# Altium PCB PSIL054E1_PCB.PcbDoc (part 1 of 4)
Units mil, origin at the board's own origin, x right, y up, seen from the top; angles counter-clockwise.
Board outline 2080 x 2700 mil, 8 copper layers (SSTXRX1, GND Plane 1, High Speed, GND Plane 2, Power 1, Power 2, GND Plane 3, SSTXRX2), stack 58.12 mil thick; 247 components, 148 nets, 834 pads, 632 vias.
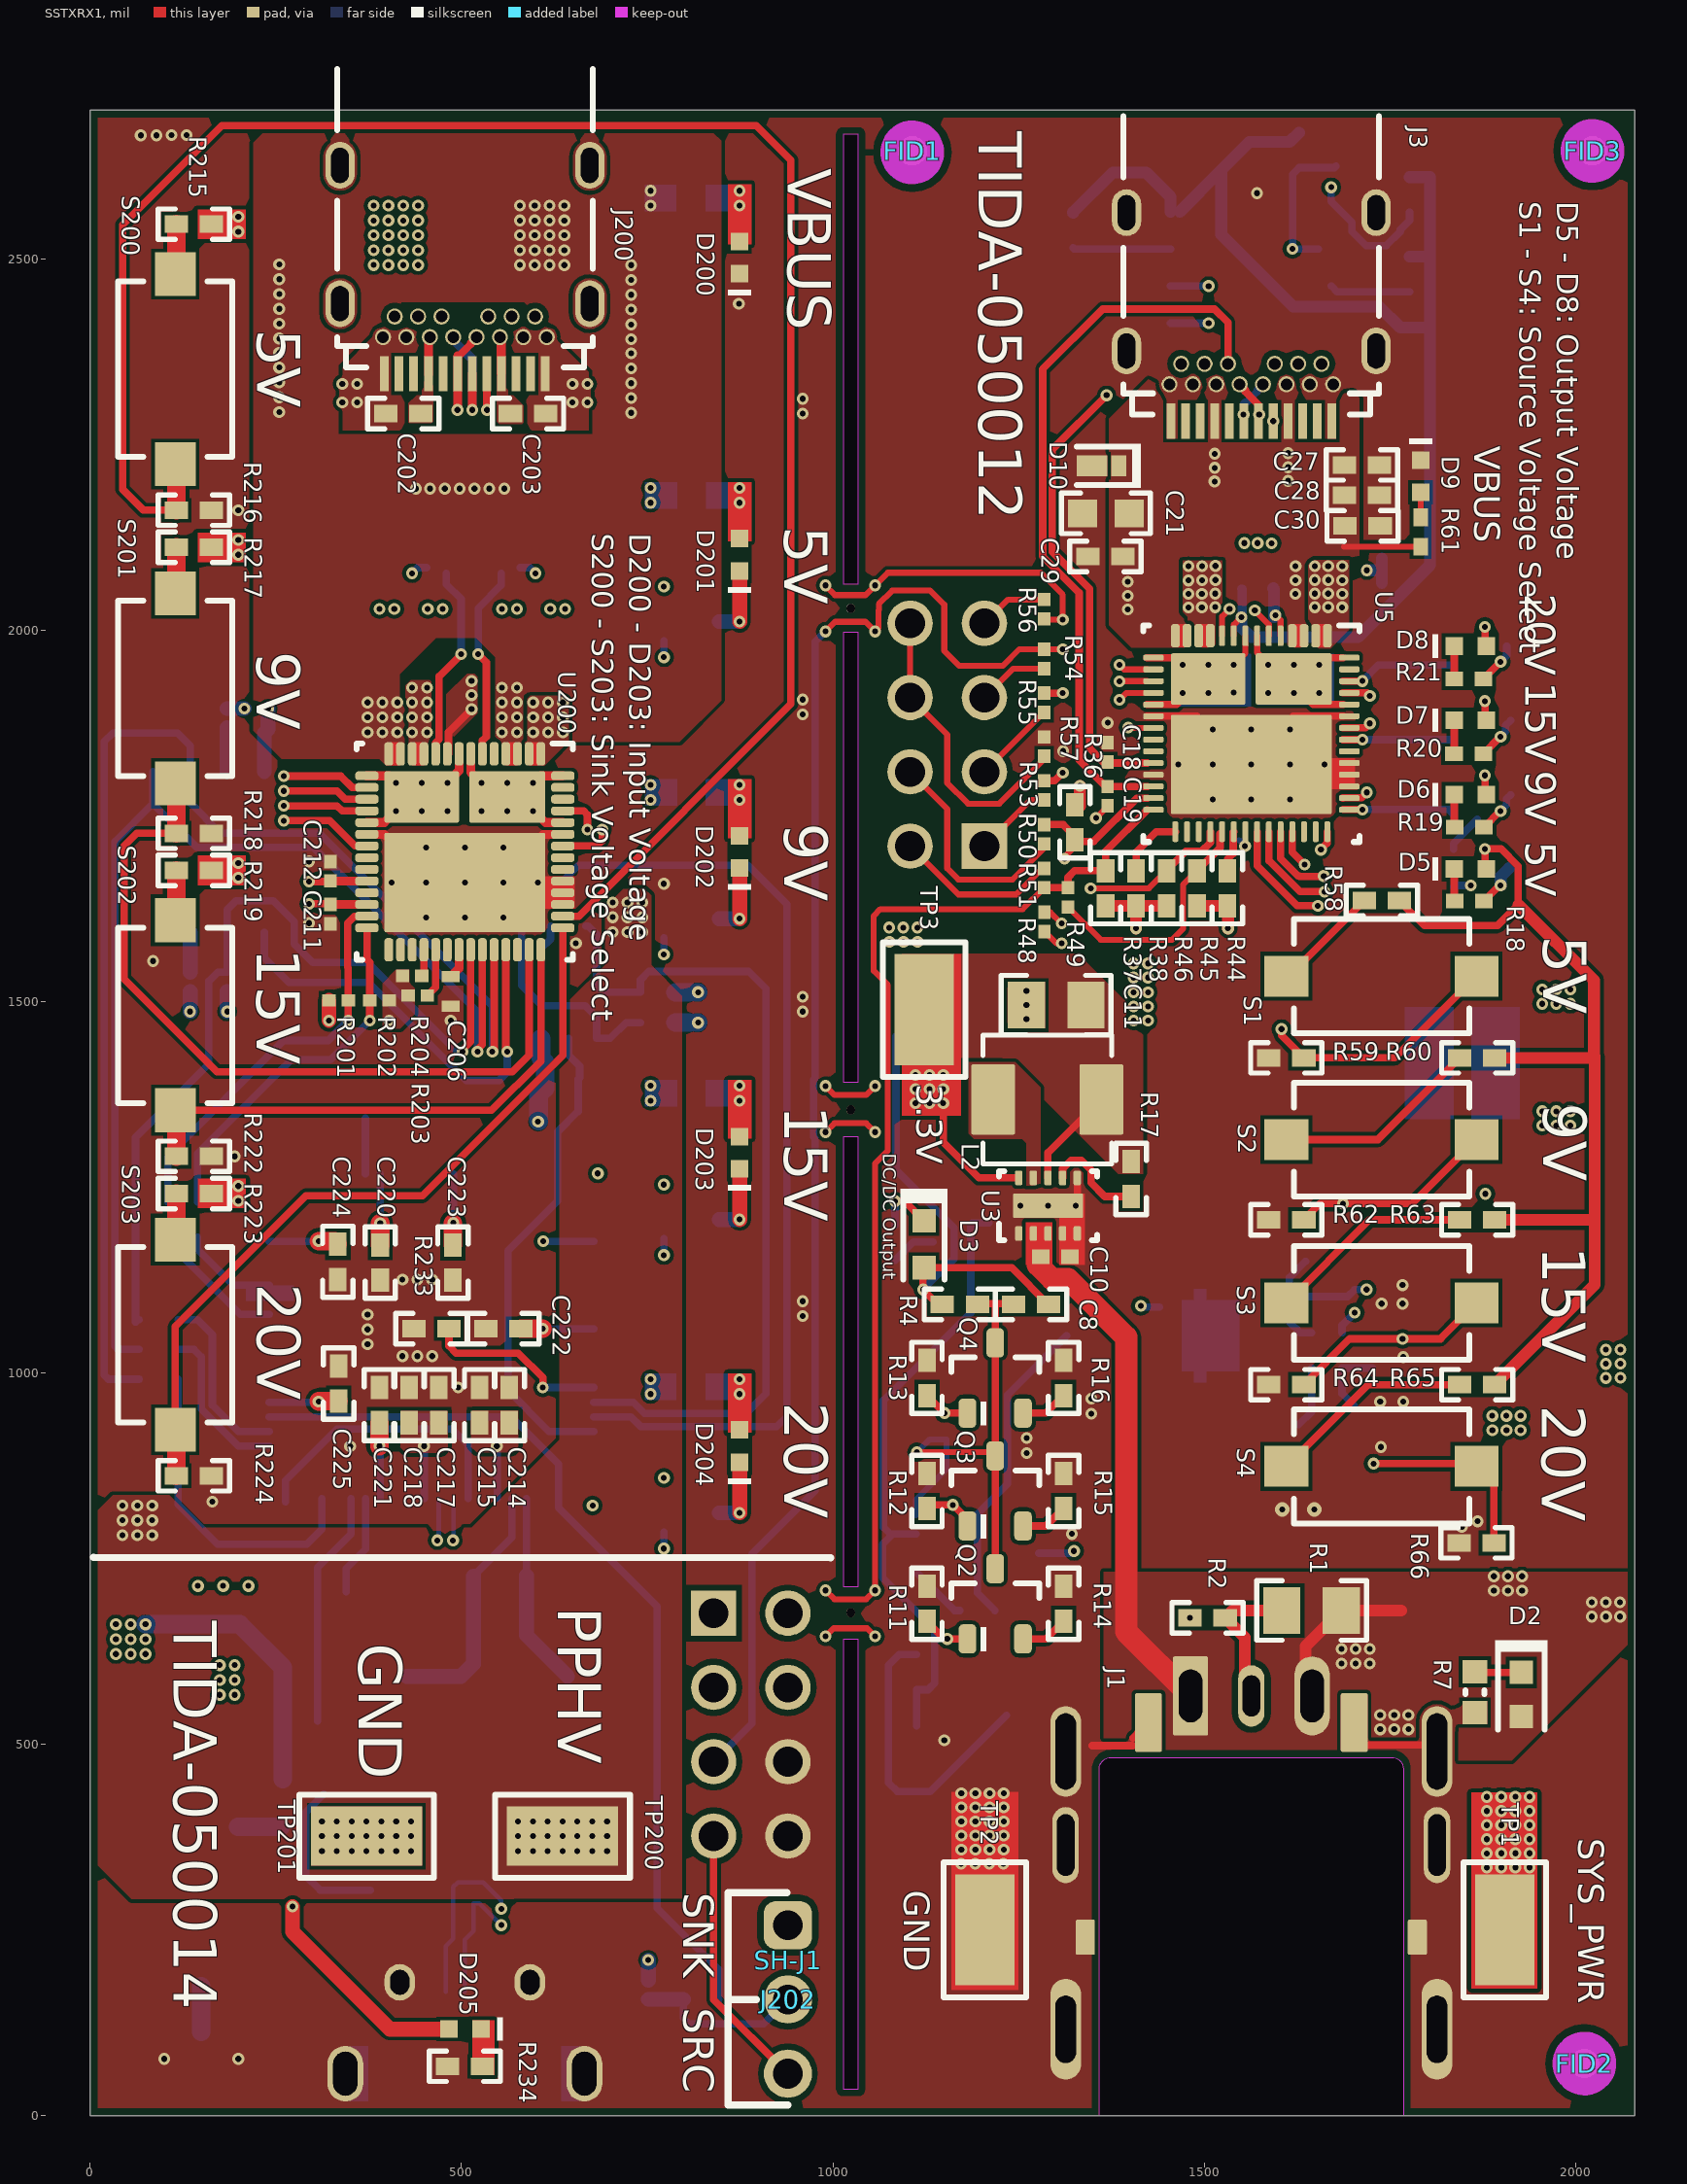
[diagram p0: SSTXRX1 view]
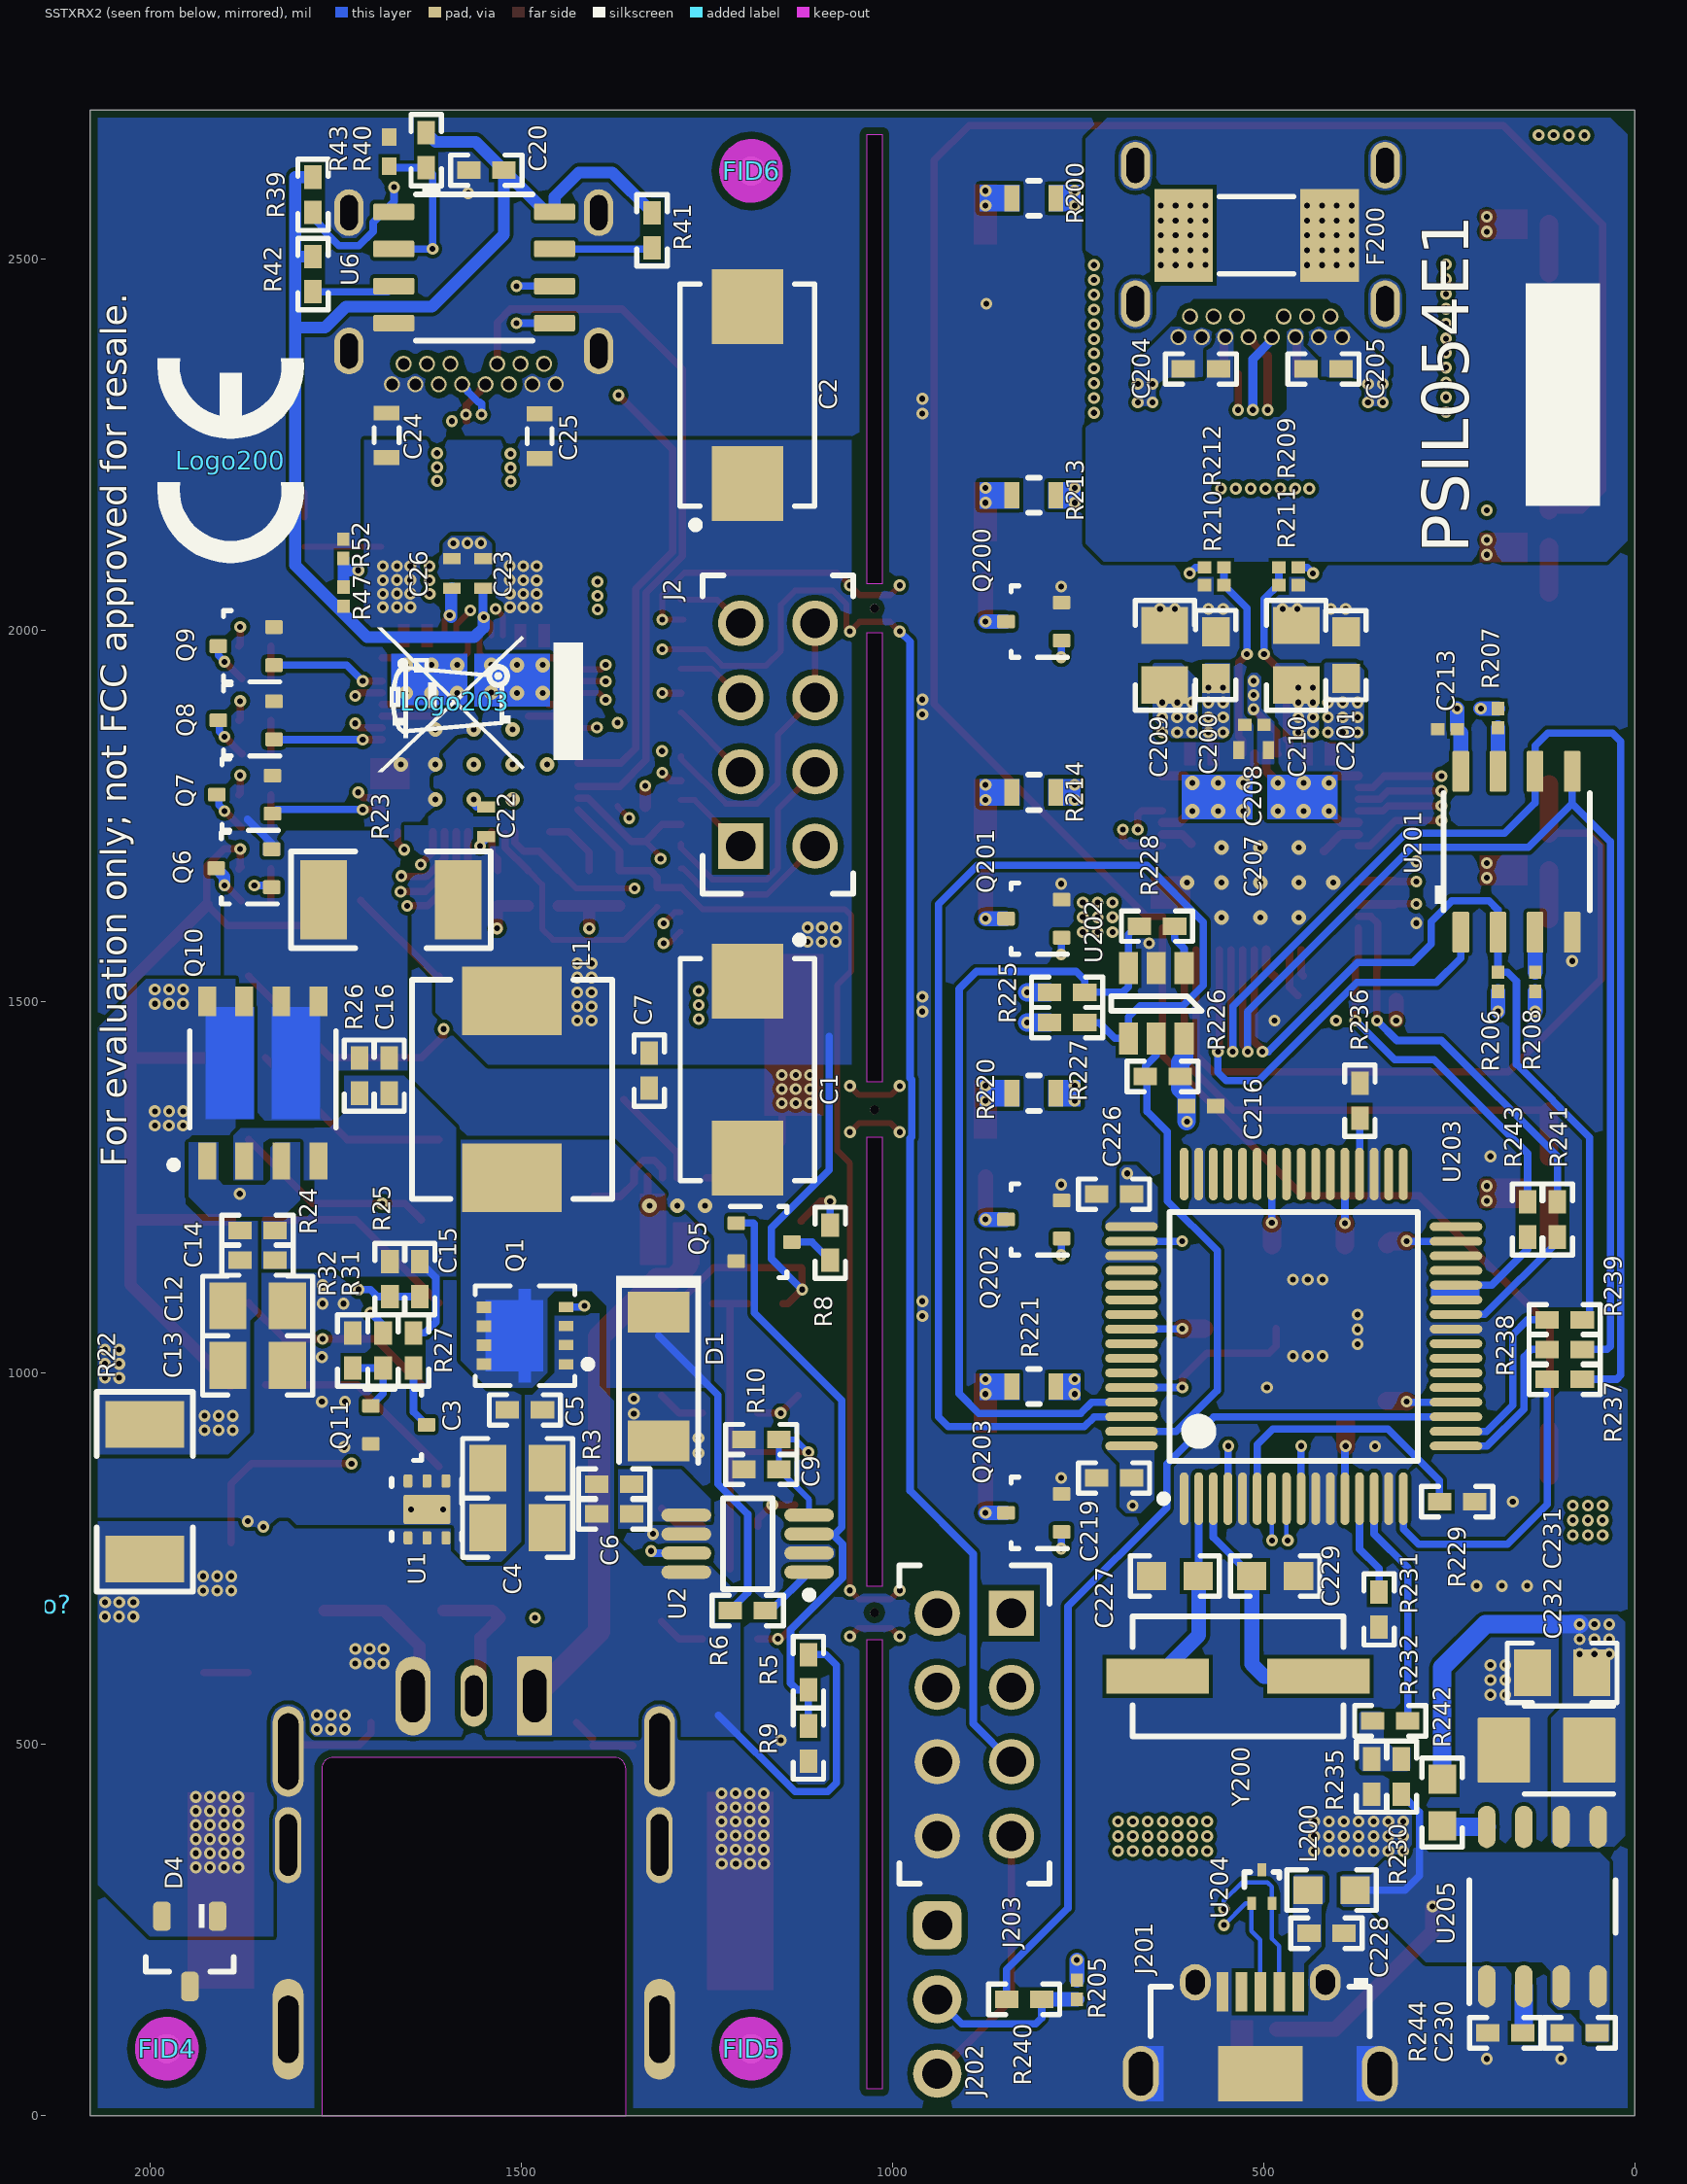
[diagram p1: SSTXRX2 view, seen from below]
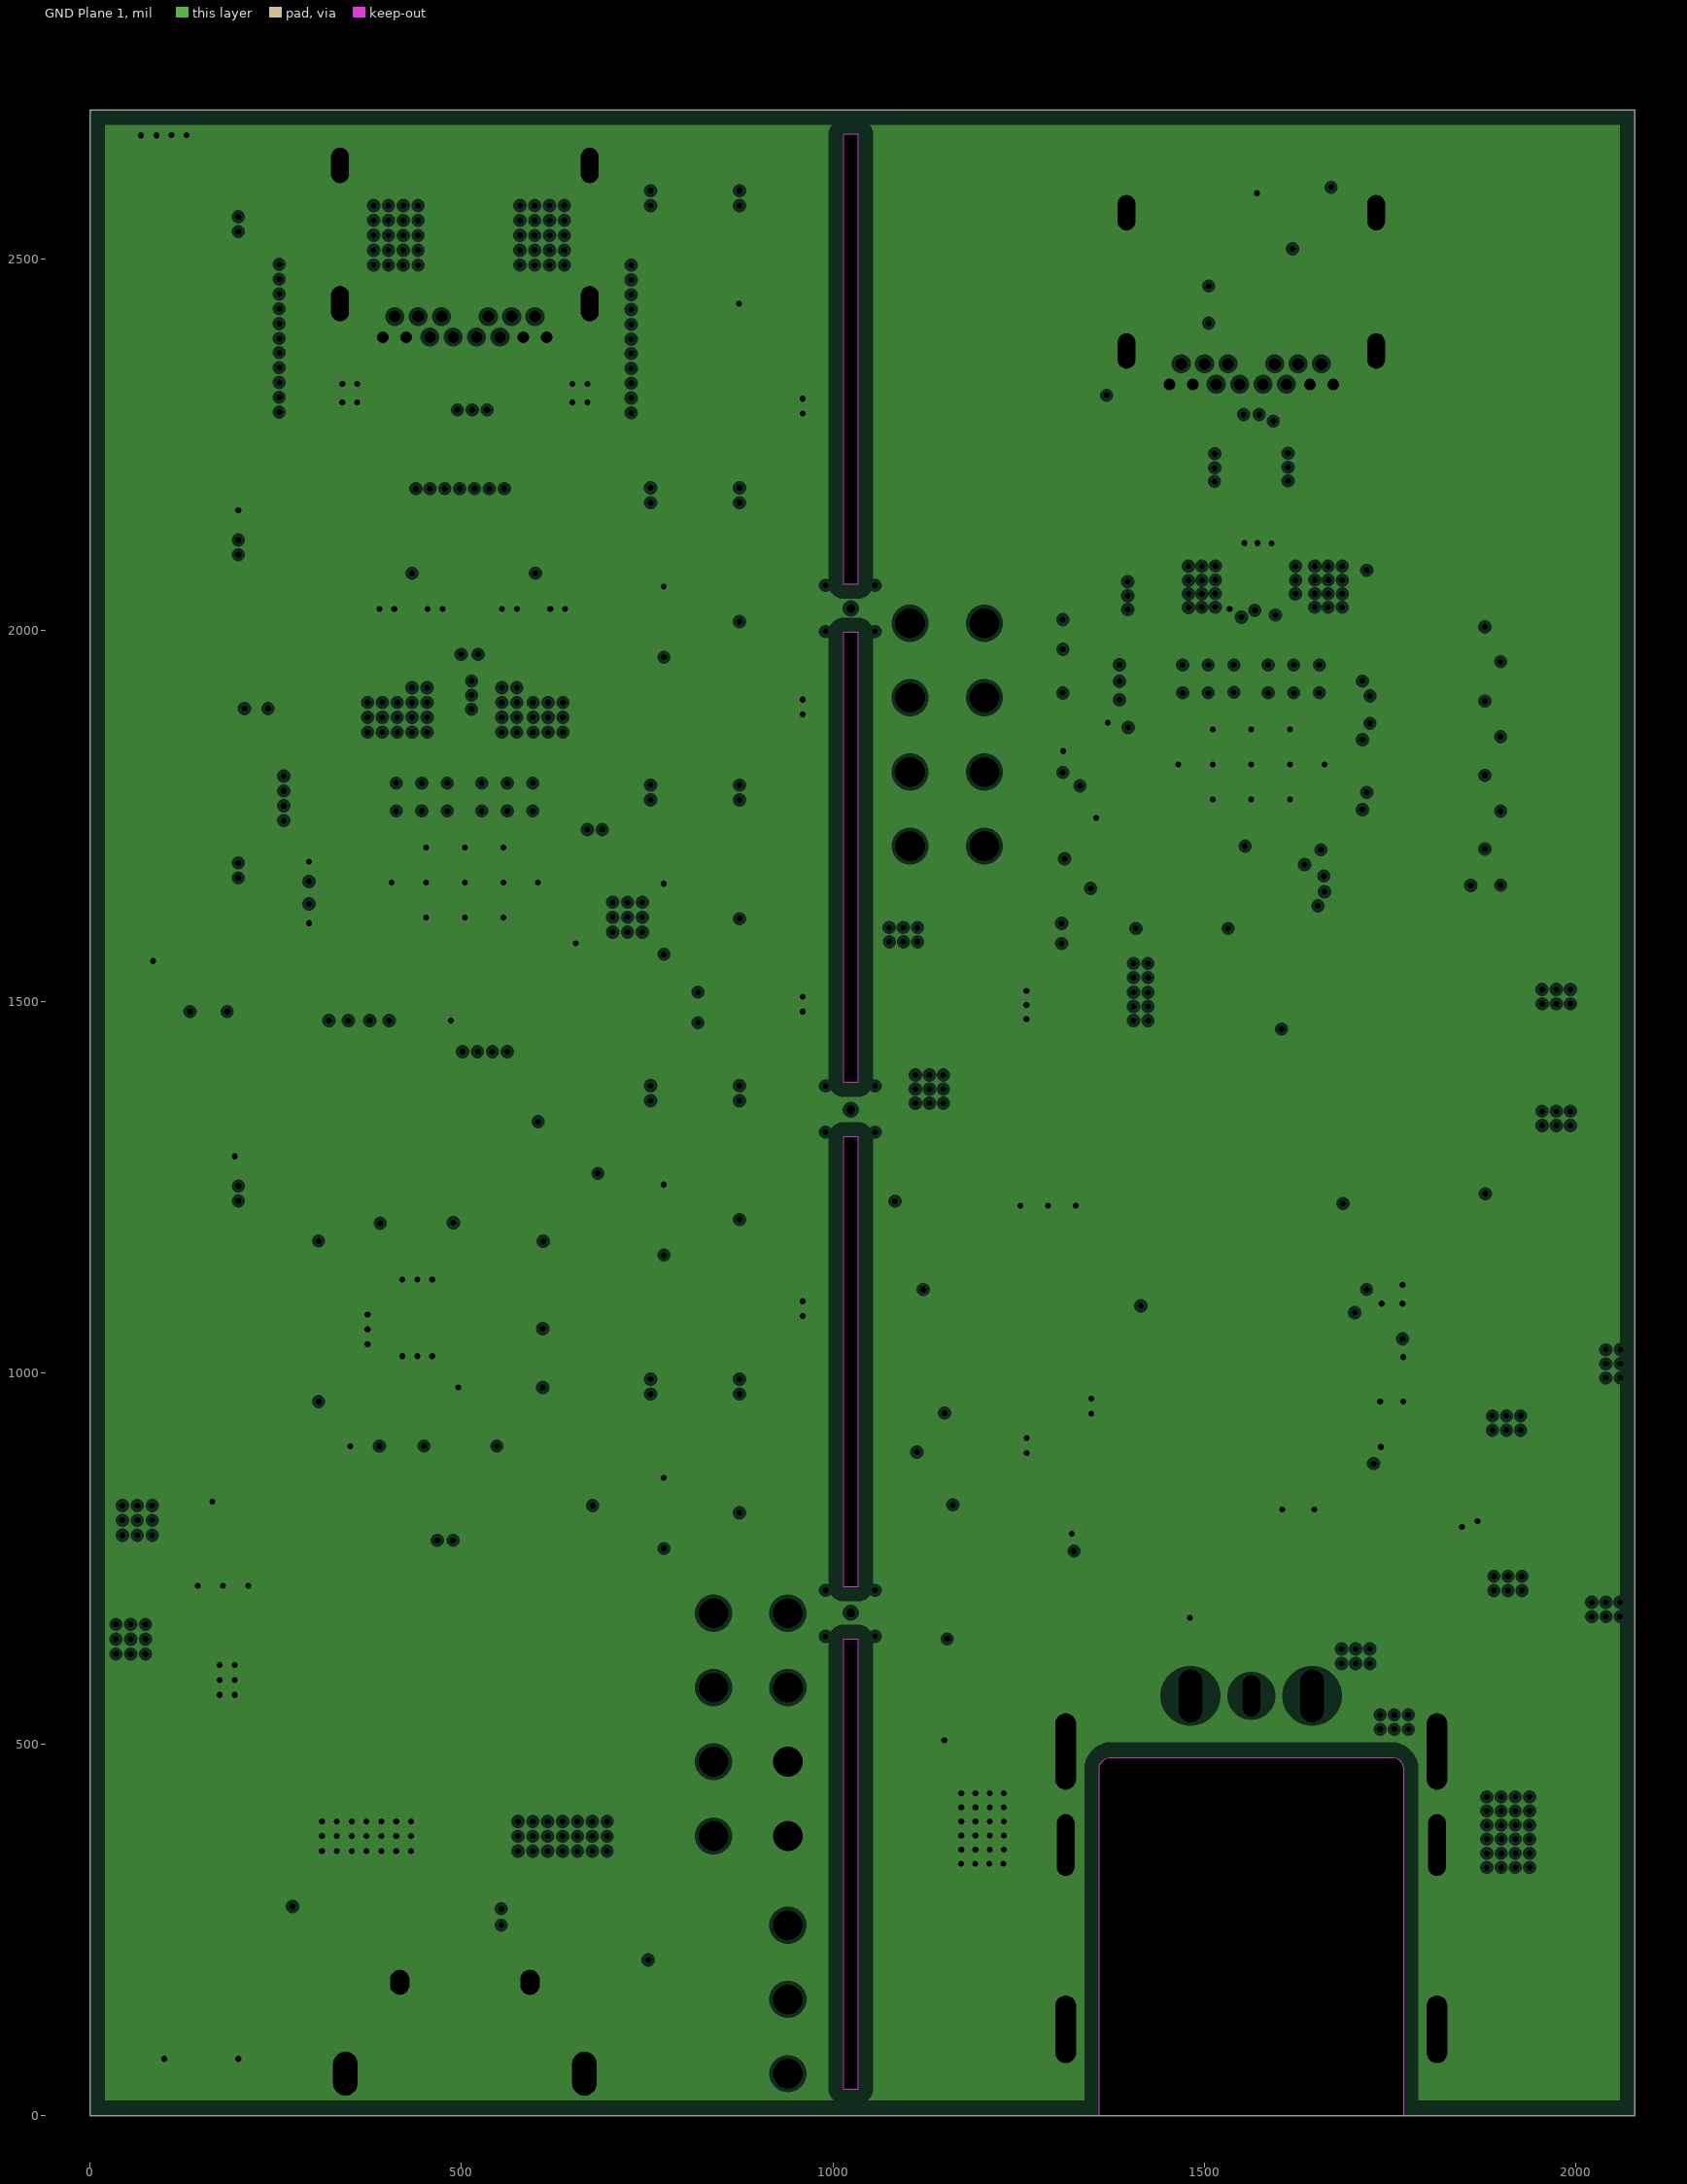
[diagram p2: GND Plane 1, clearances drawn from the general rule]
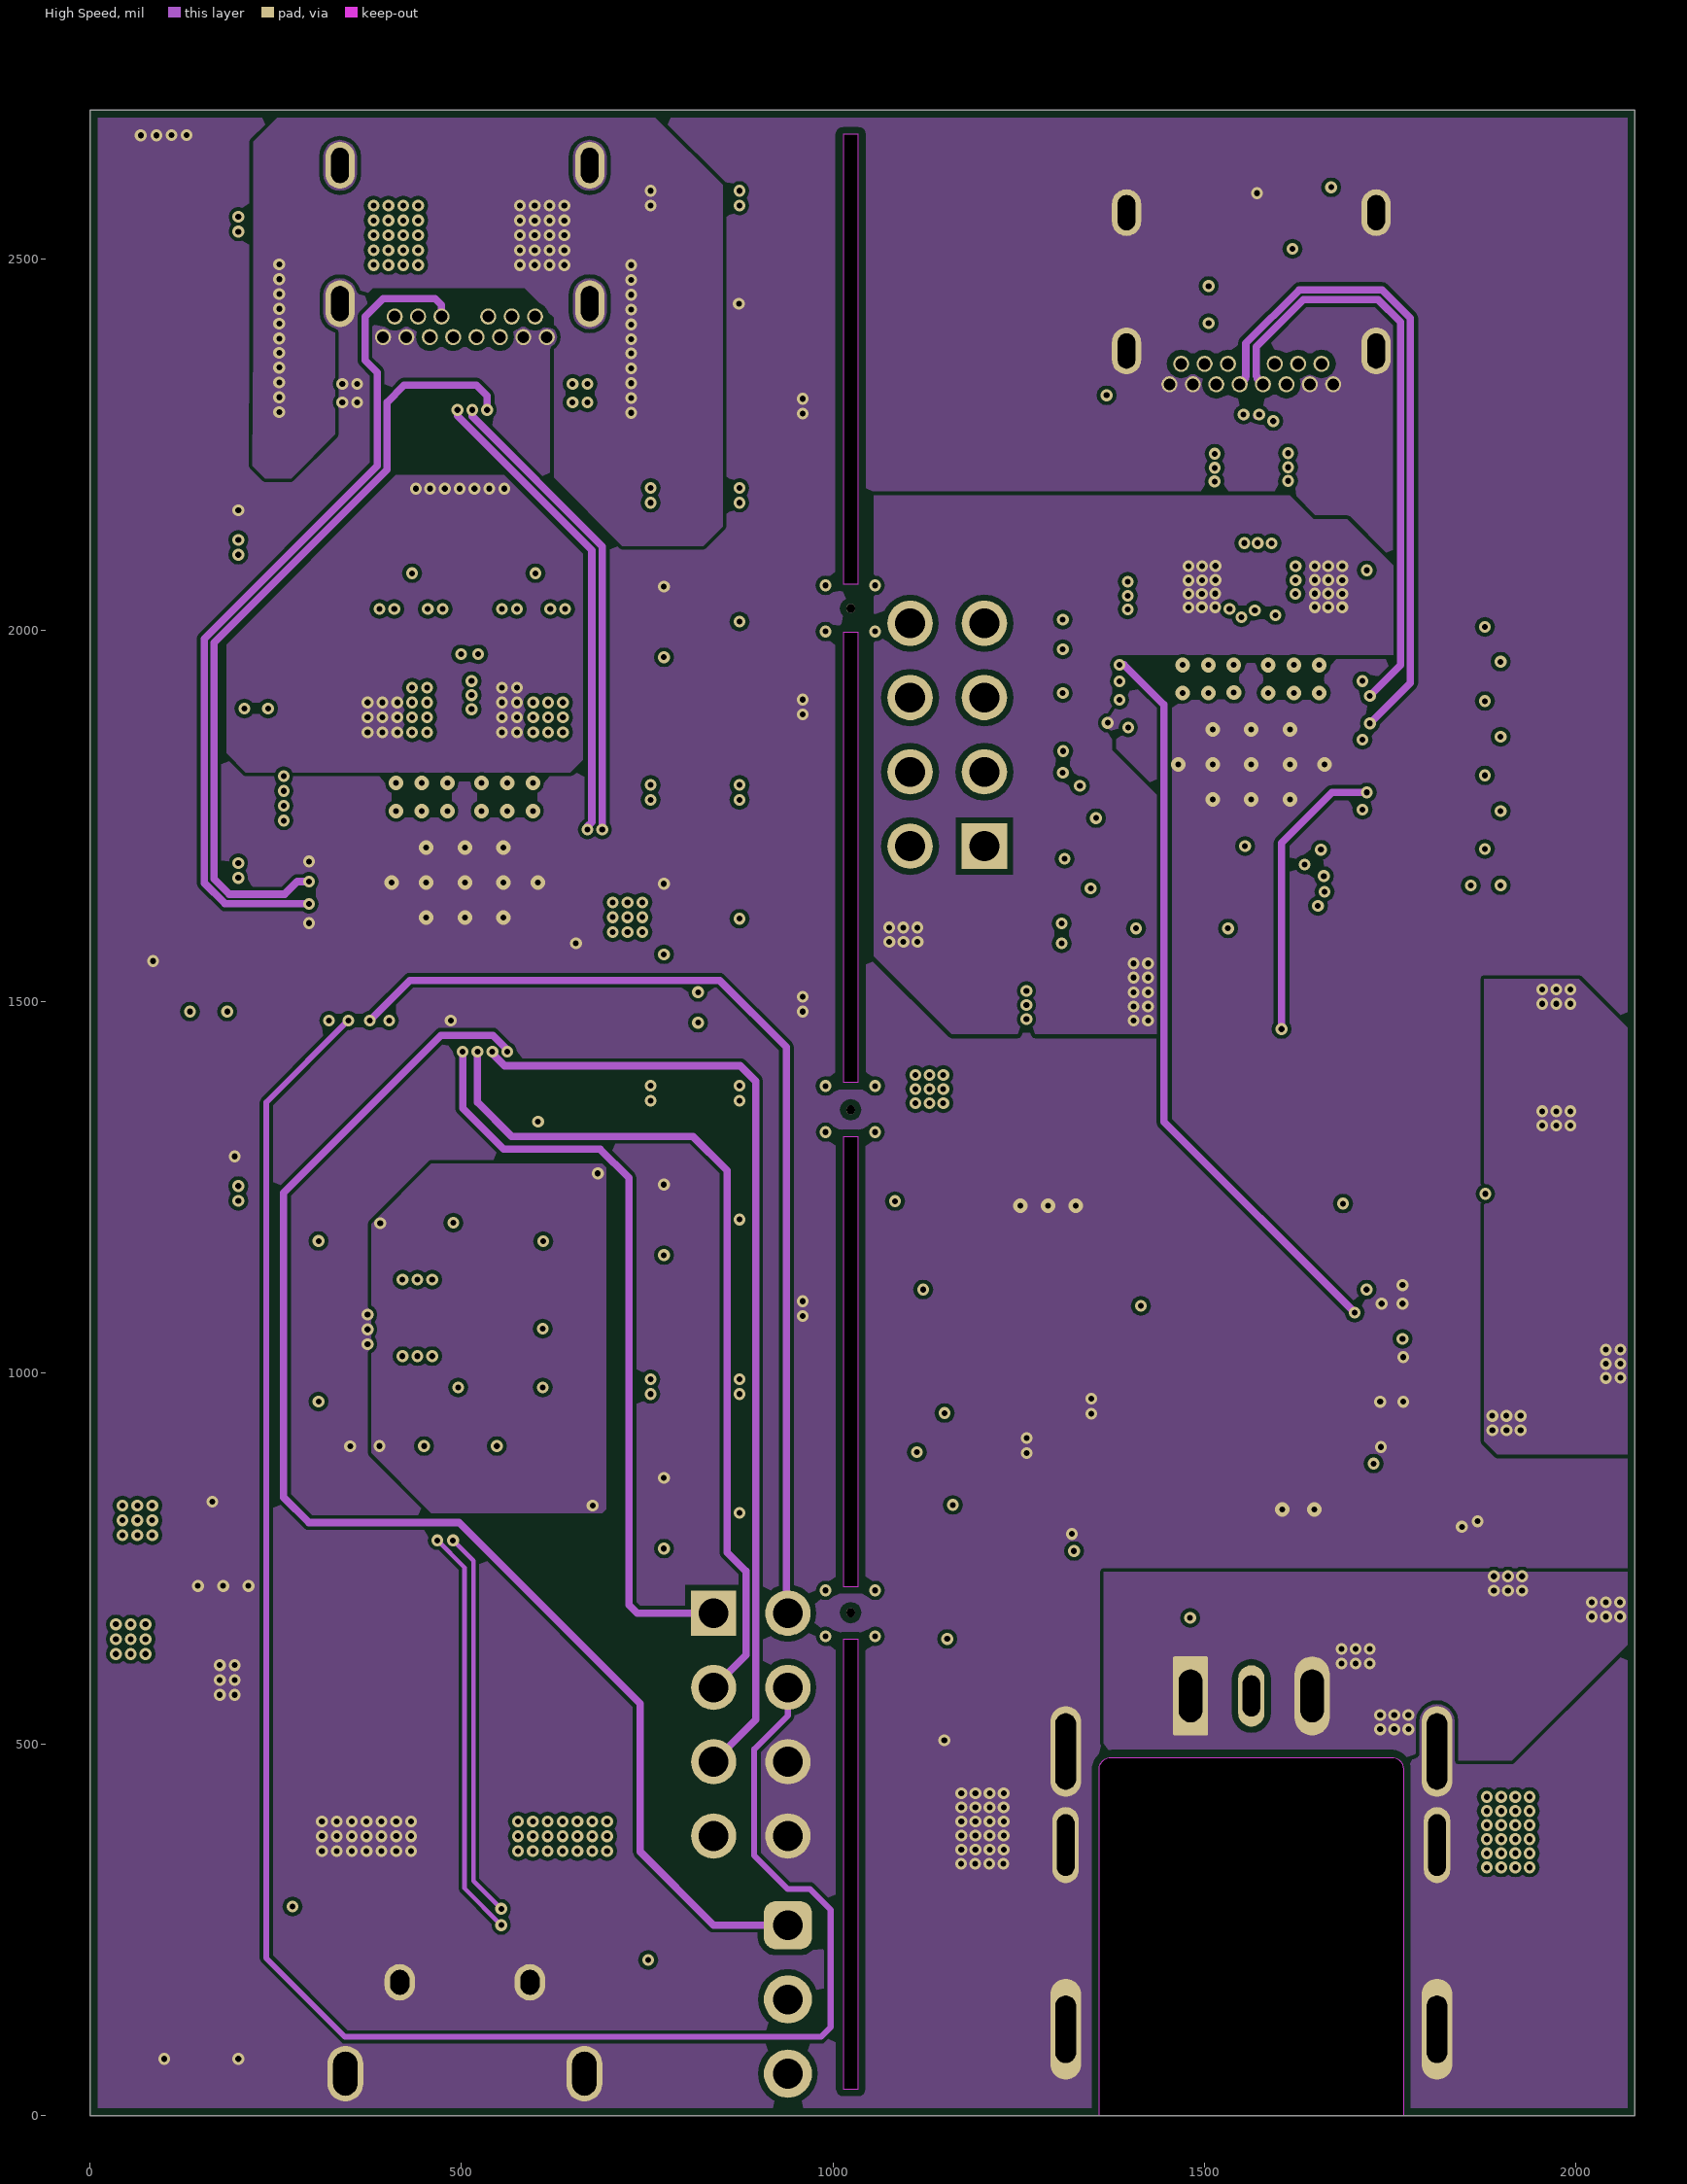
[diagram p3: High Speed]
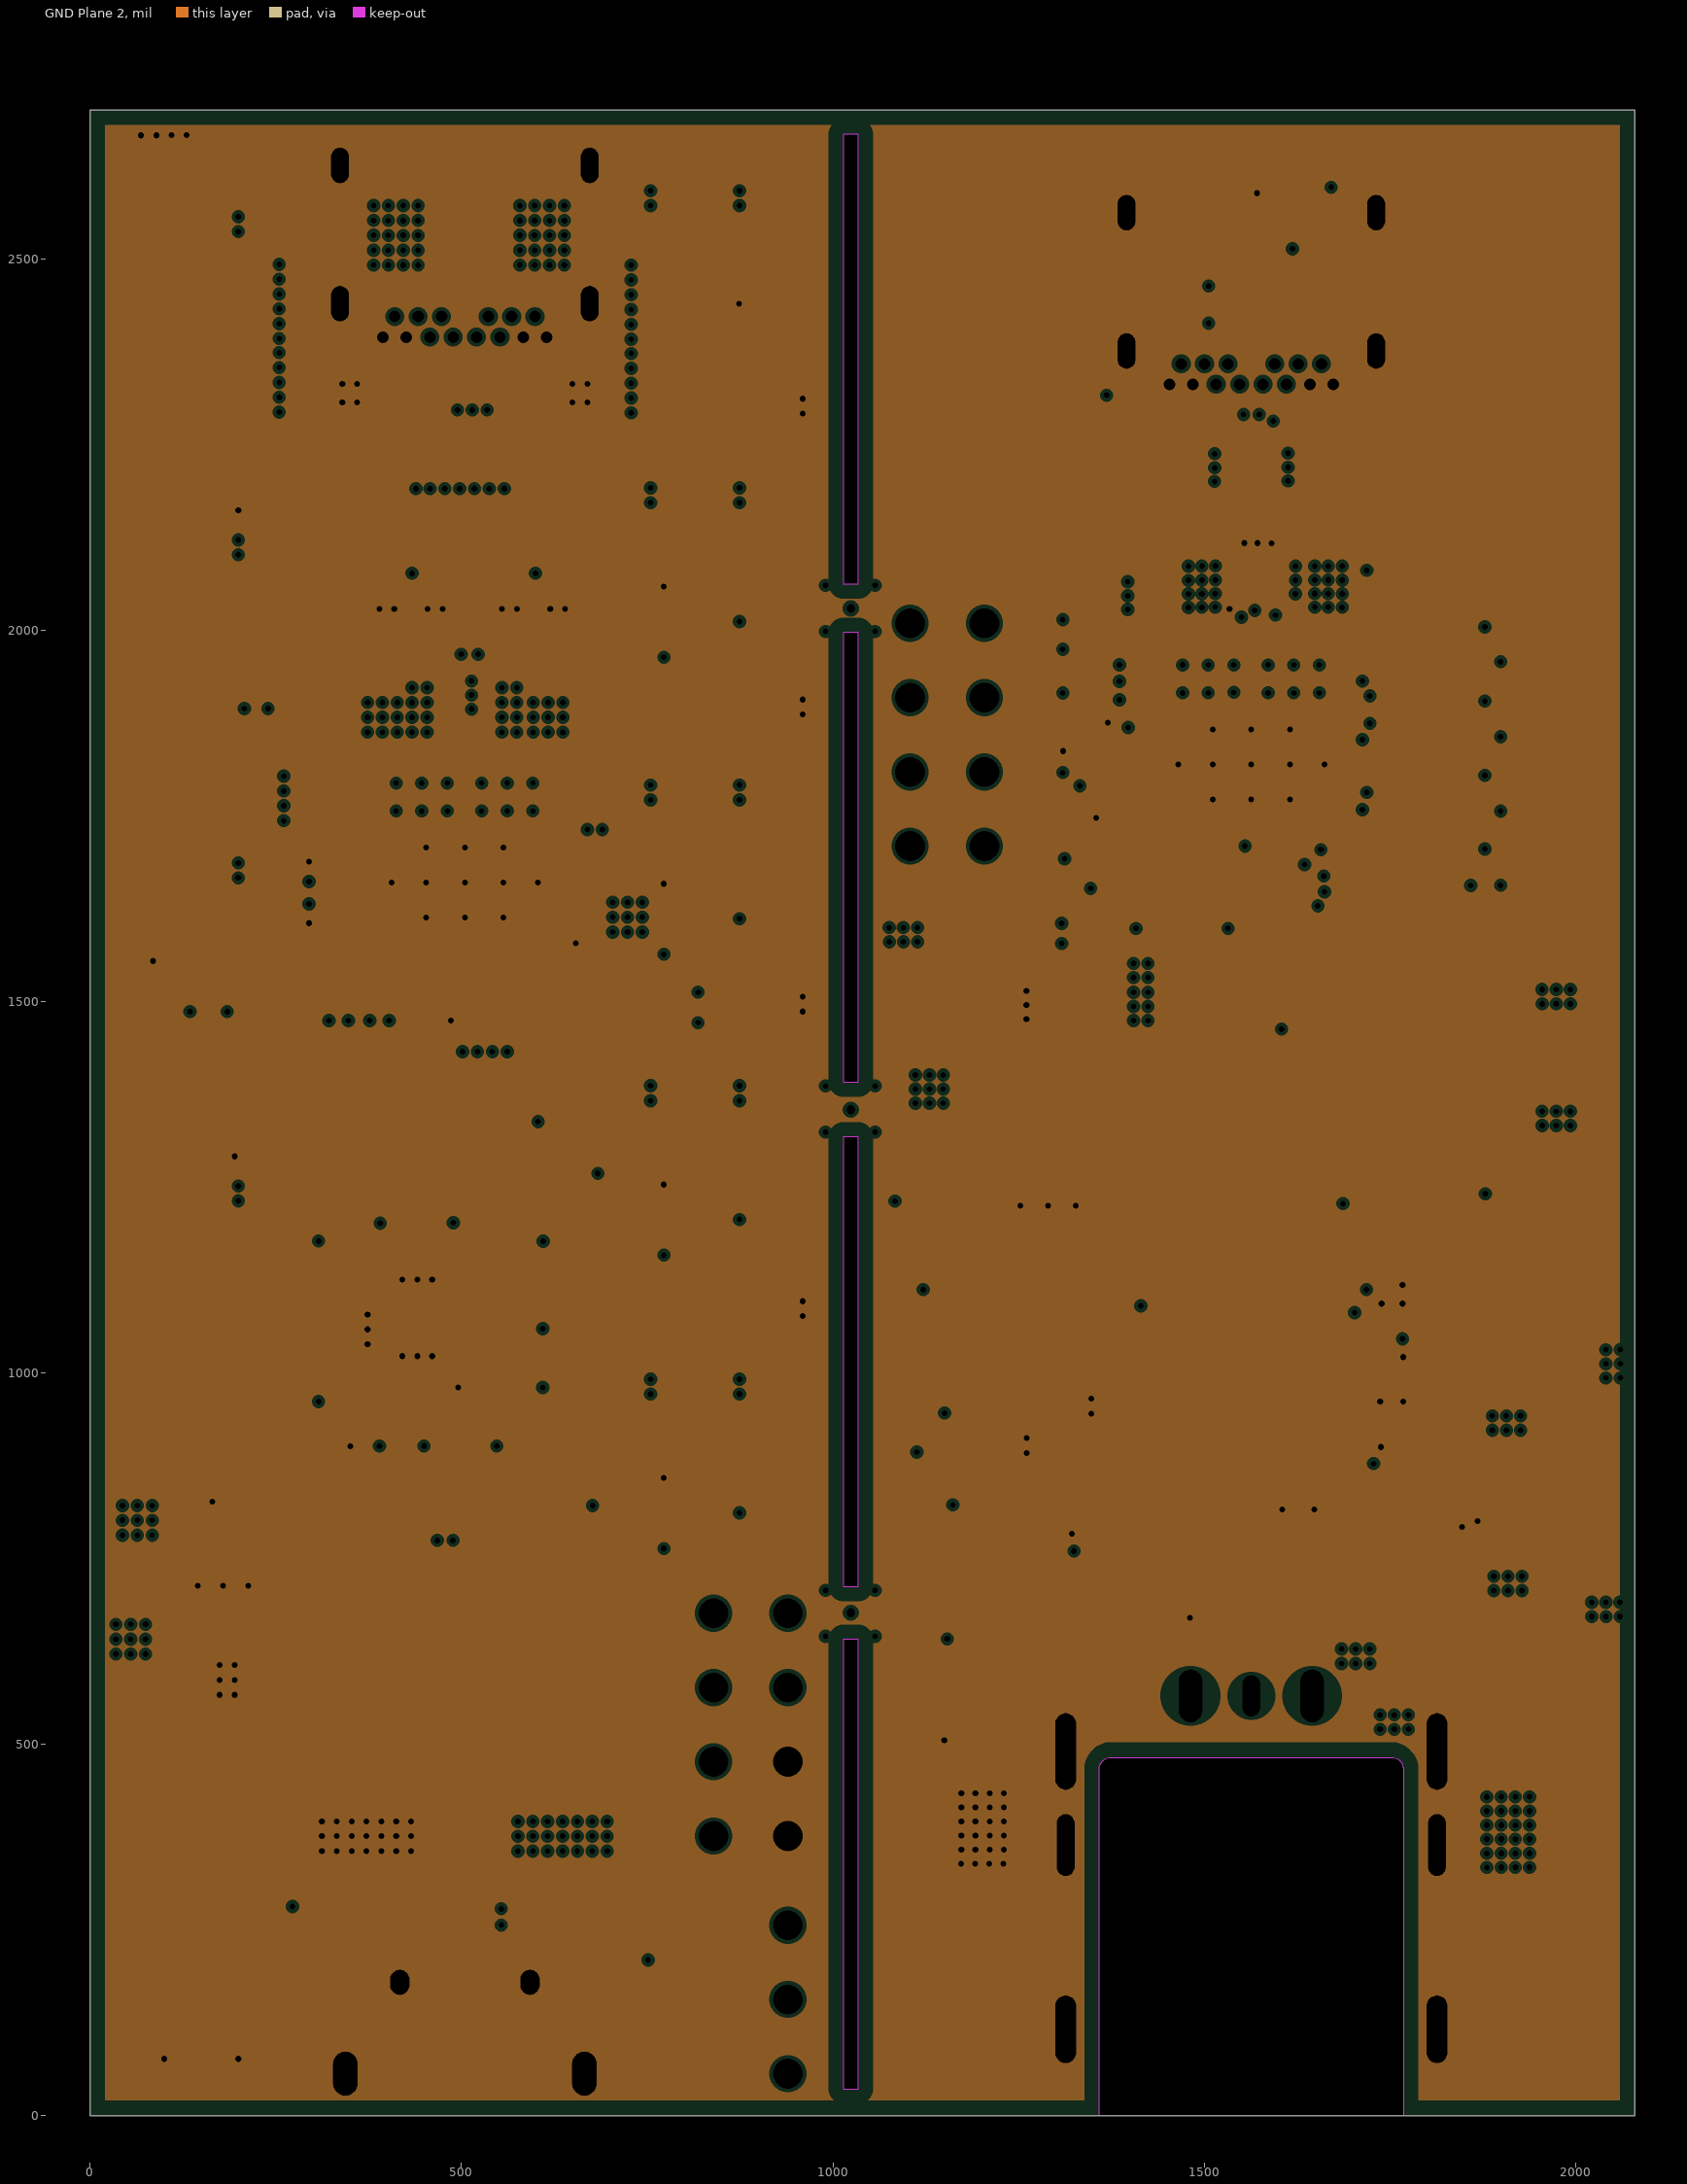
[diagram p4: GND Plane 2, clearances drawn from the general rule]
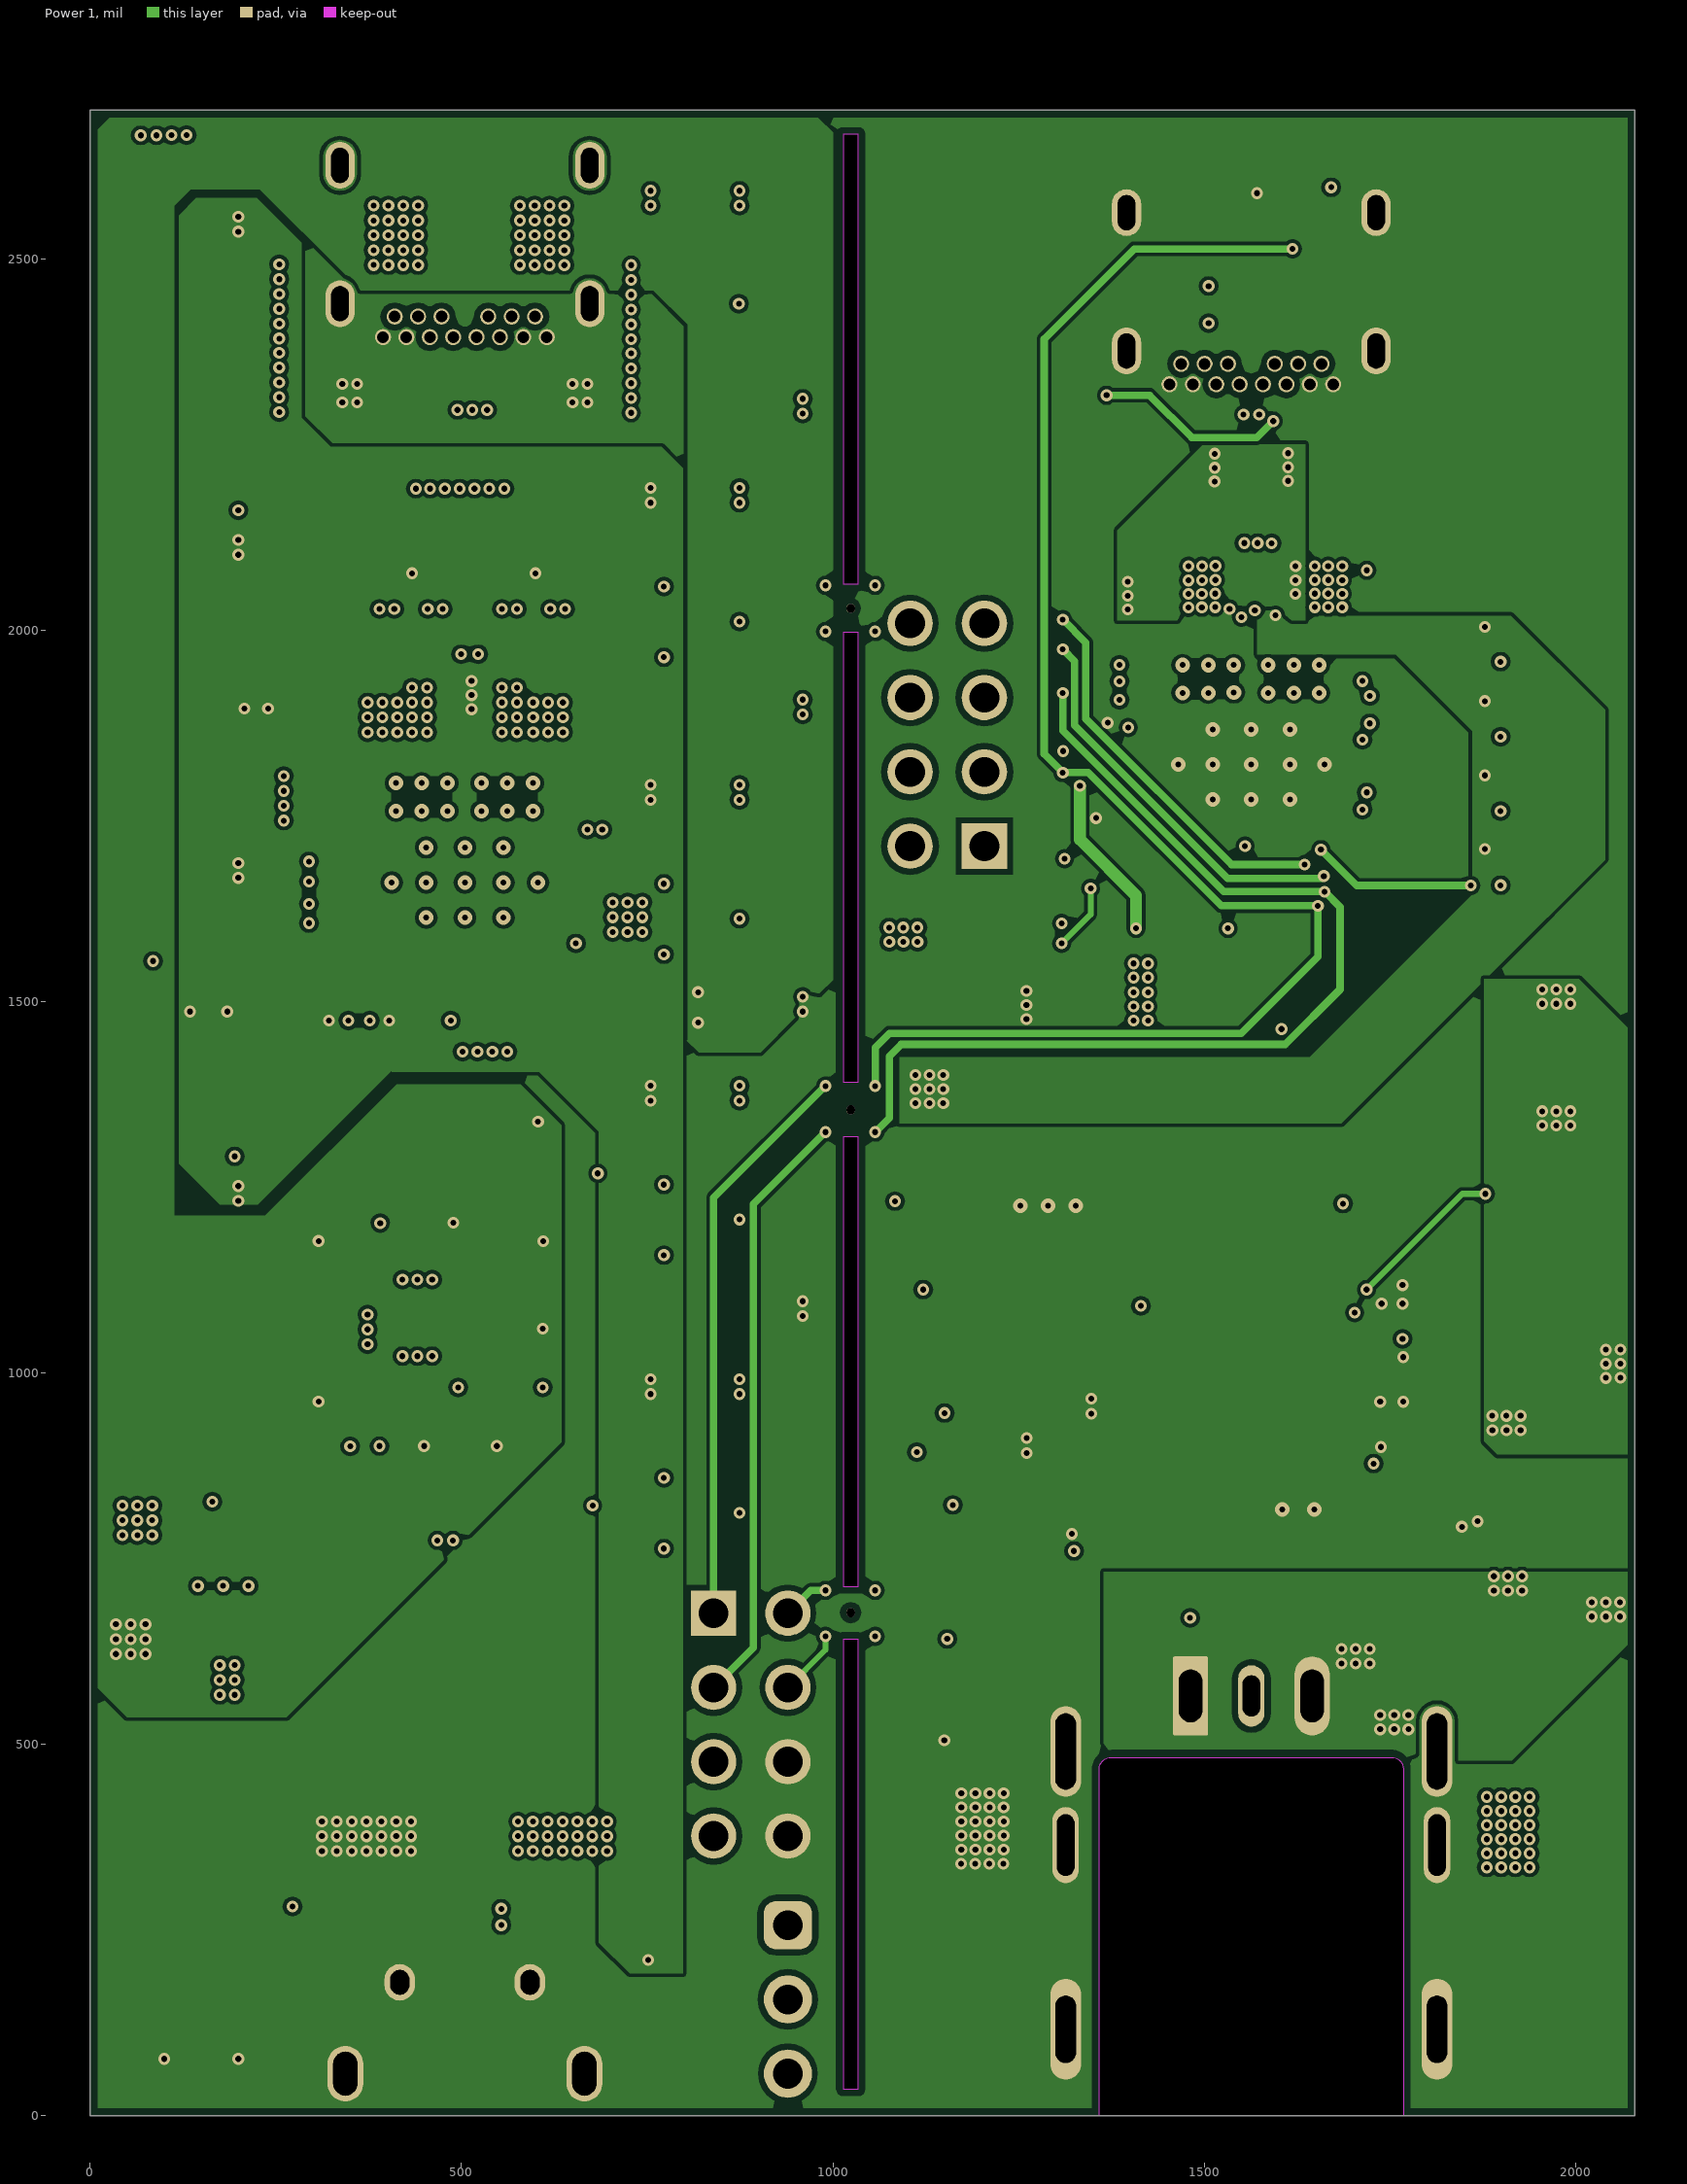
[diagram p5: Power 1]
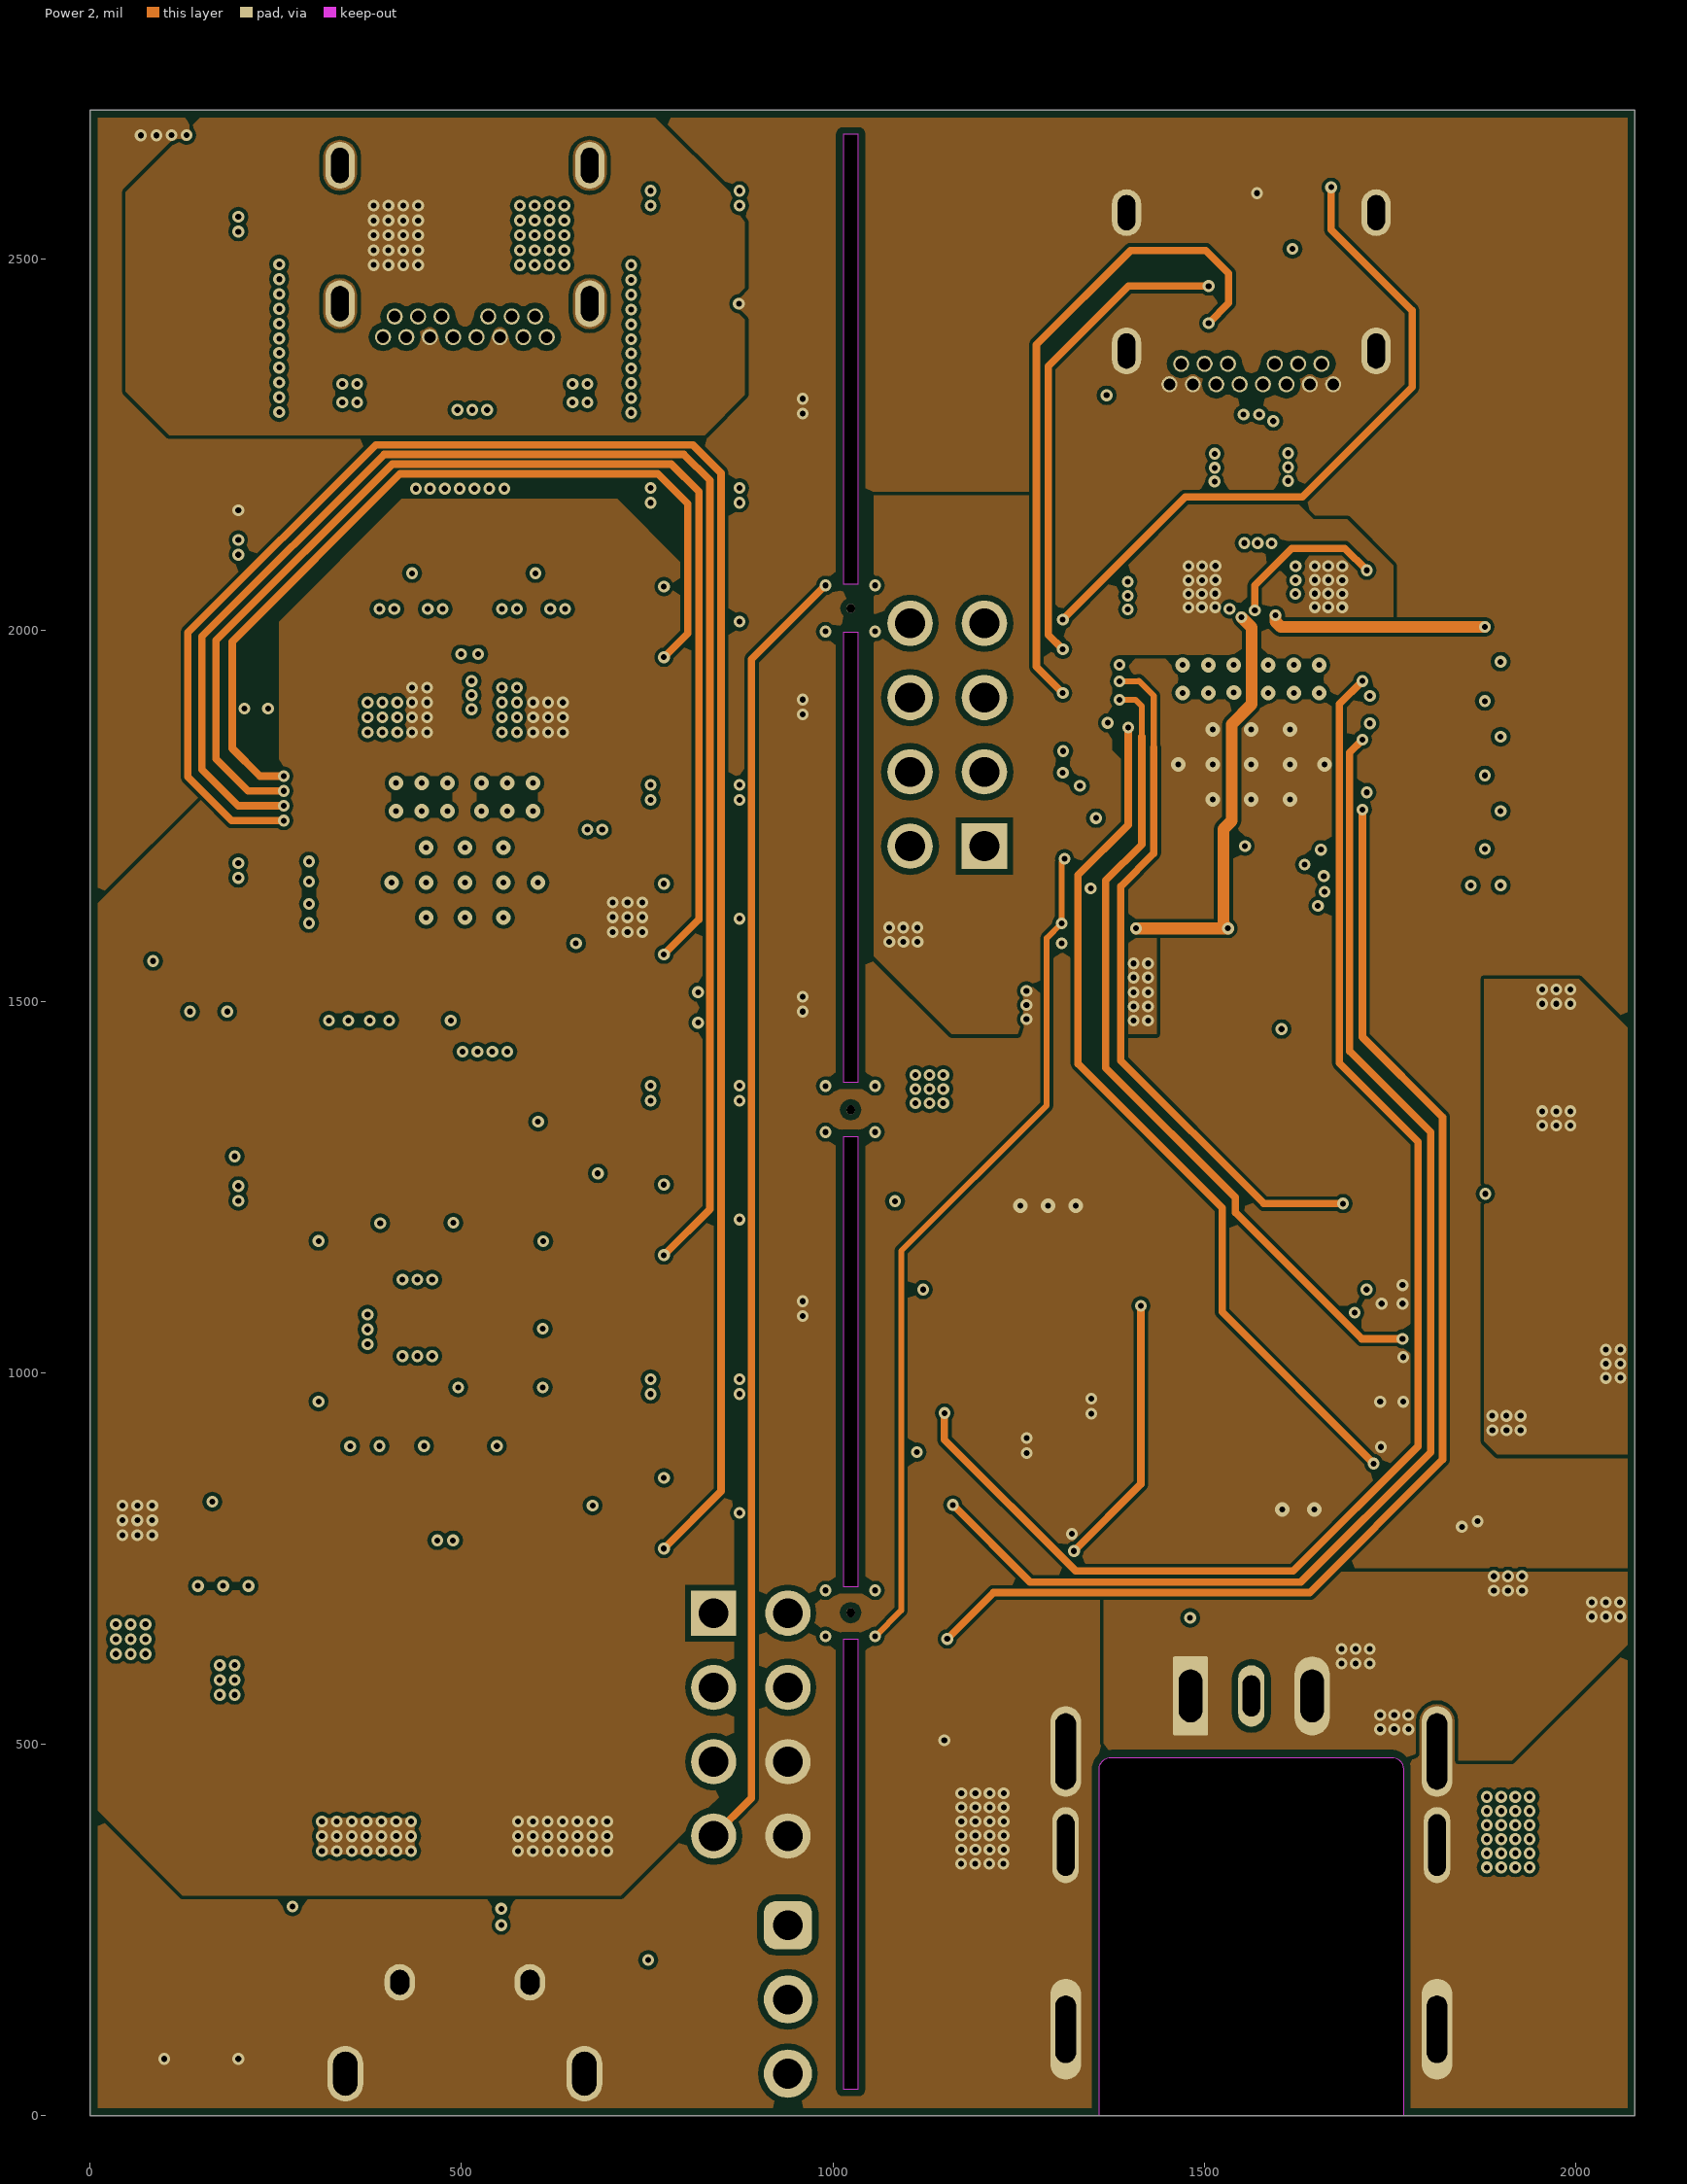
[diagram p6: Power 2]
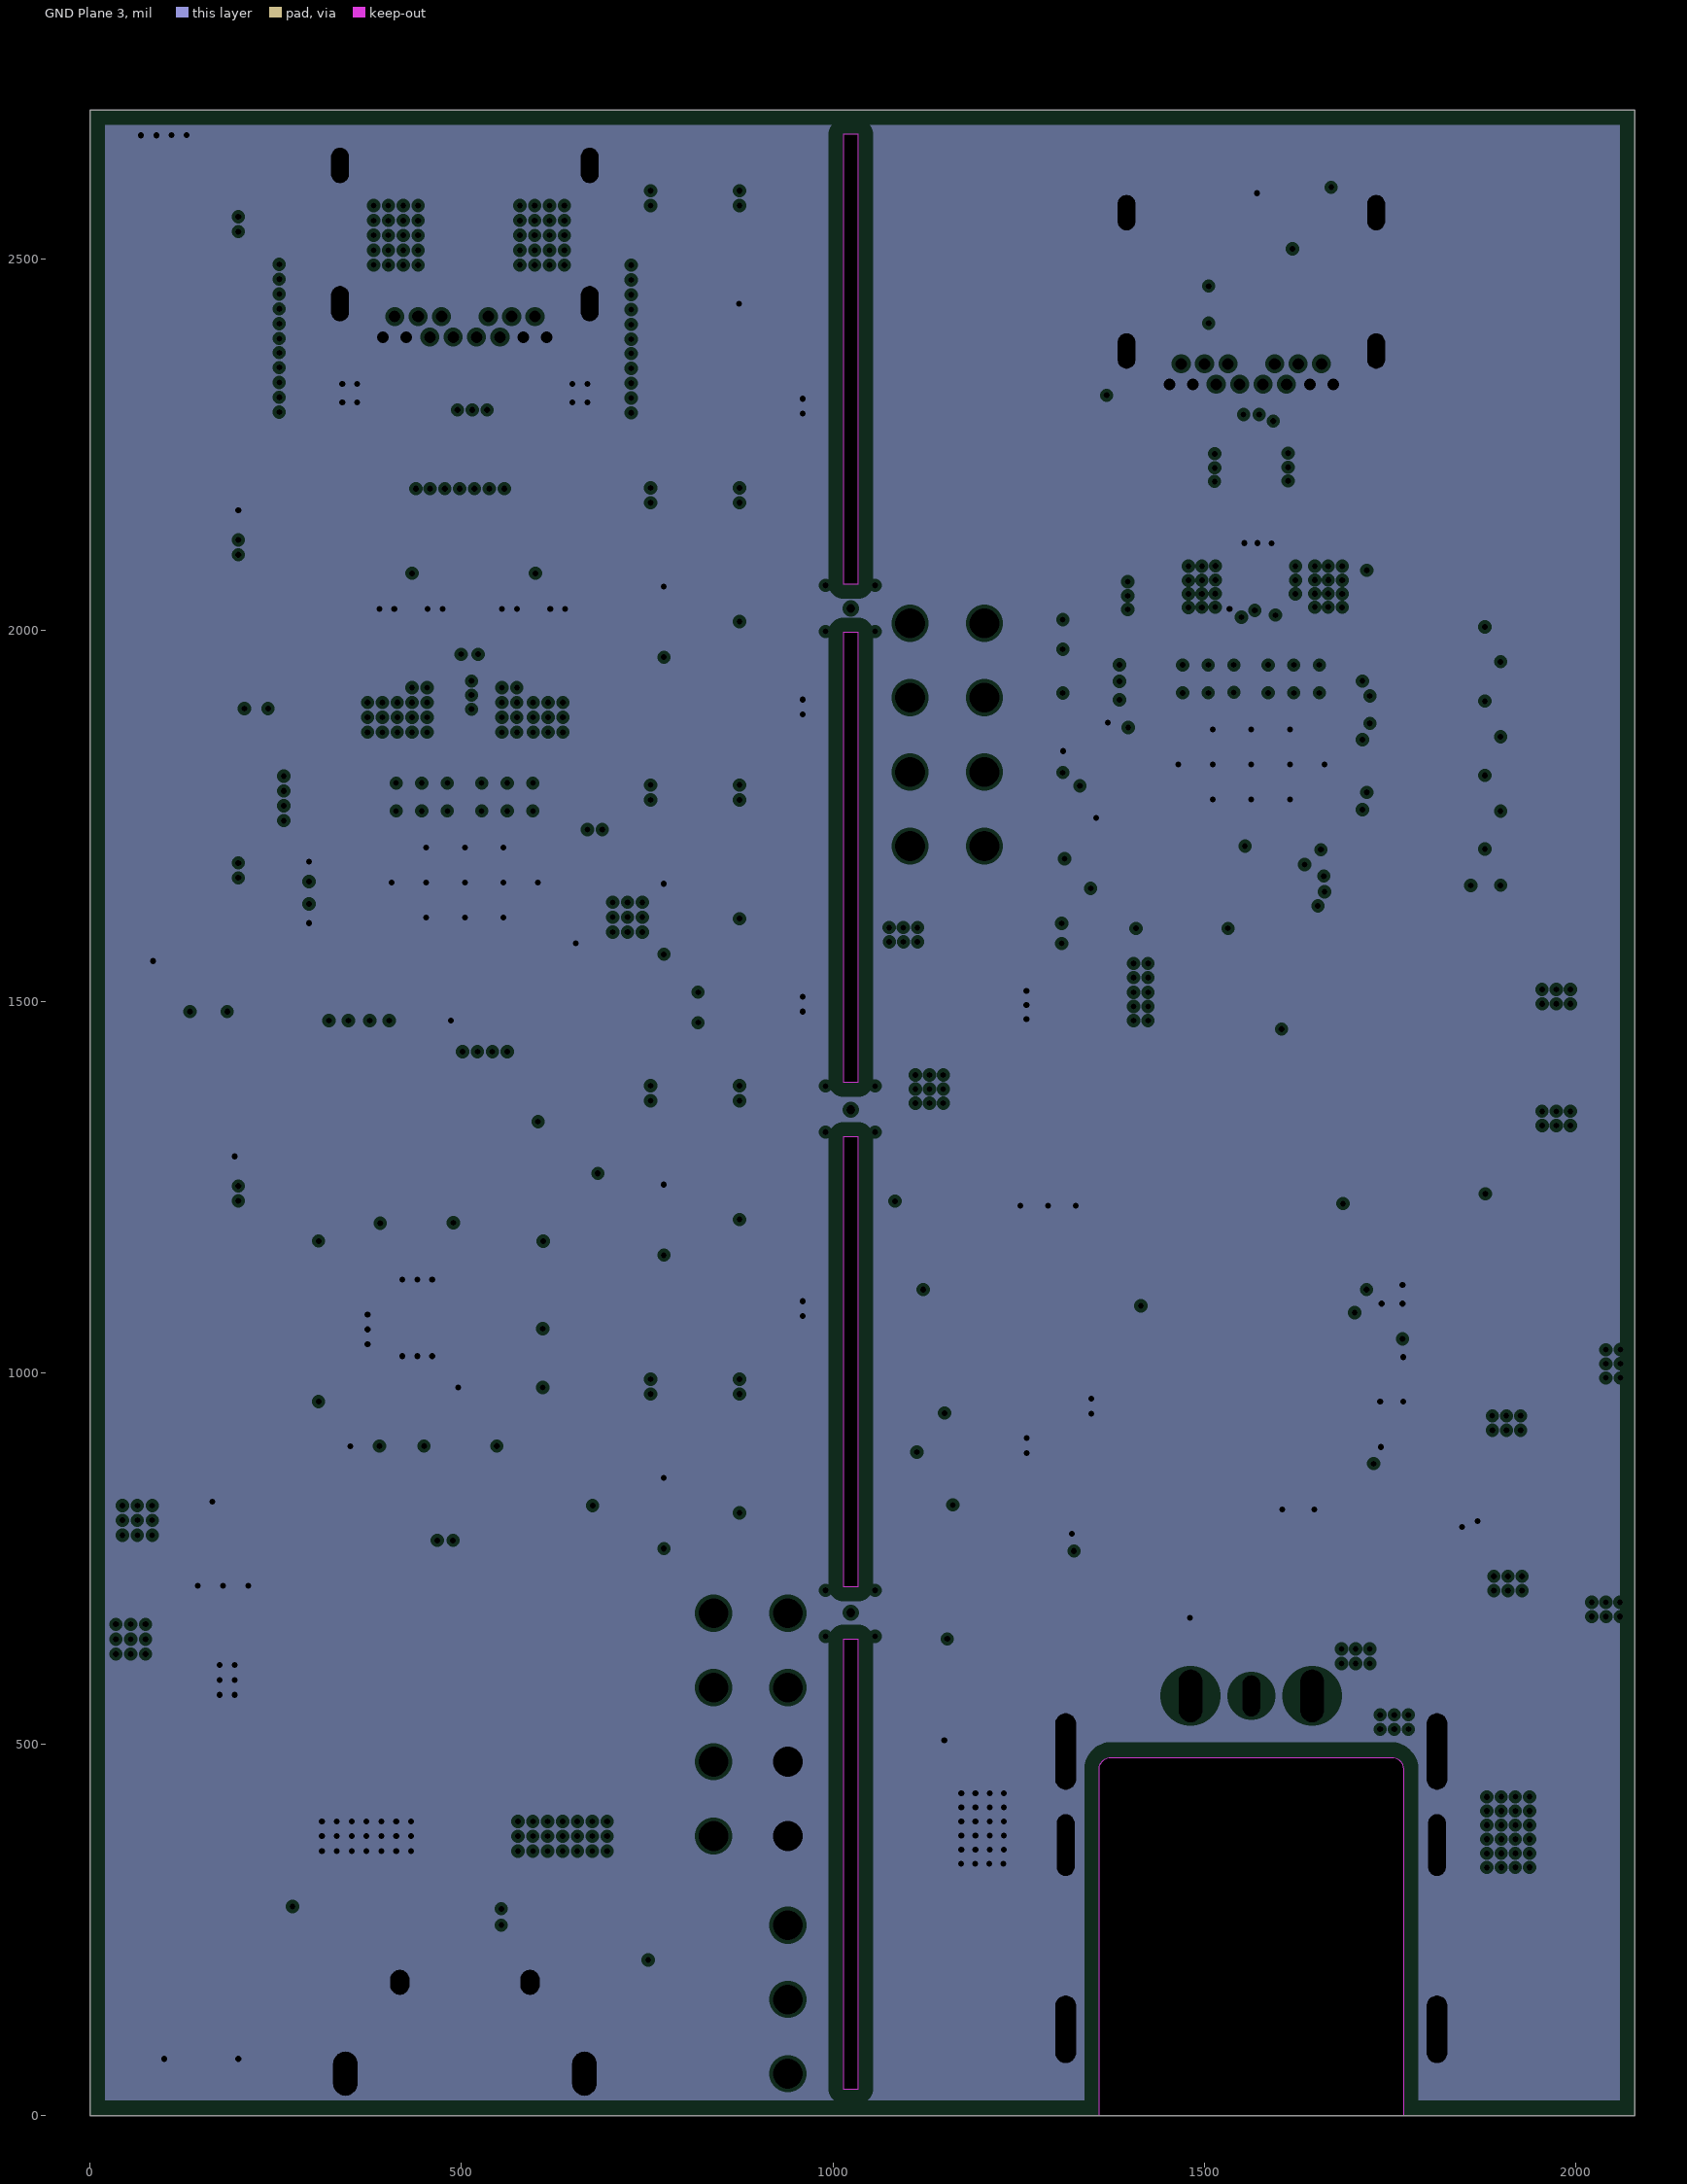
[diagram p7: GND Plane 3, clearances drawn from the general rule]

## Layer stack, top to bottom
Top Solder: solder mask 0.45, Solder Resist, Dk 3
SSTXRX1: signal copper 1.4
Dielectric1: core 4.92, FR-4, Dk 4.1
GND Plane 1: plane copper 0.7, net GND
Dielectric 2: prepreg 7.87, FR-4, Dk 4.1
High Speed: signal copper 0.7
Dielectric 3: core 7.87, FR-4, Dk 4.1
GND Plane 2: plane copper 0.7, net GND
Dielectric 4: prepreg 9.8, FR-4, Dk 4.1
Power 1: signal copper 0.7
Dielectric 5: core 7.87, FR-4, Dk 4.1
Power 2: signal copper 0.7
Dielectric 6: prepreg 7.87, FR-4, Dk 4.1
GND Plane 3: plane copper 0.7, net GND
Dielectric 7: core 4.92, FR-4, Dk 4.1
SSTXRX2: signal copper 1.4
Bottom Solder: solder mask 0.45, Solder Resist, Dk 3

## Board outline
0,0 2080,0 2080,2700 0,2700
cut-out: 1034,1317.5 1014,1317.5 1014,712.5 1034,712.5
cut-out: 1034,641 1014,641 1014,36 1034,36
cut-out: 1034,1996.5 1014,1996.5 1014,1391.5 1034,1391.5
cut-out: 1034,2667 1014,2667 1014,2062 1034,2062

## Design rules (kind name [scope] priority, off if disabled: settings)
AcuteAngle [All] p1: minimum=4.50000000000000E+0001 checktracksonly=FALSE
AssemblyTestPointUsage [All] p1: valid=2
BoardOutlineClearance [OnCopper] p1: gap=10 ignorepadtopadclearanceinfootprint=FALSE except(0: Text-OutlineEdge Text-CavityEdge Text-CutoutEdge Text-SplitBarrior Text-SplitContinuation)
Clearance Clearance_Keepouts [((IsTrack Or IsArc) And Not InPoly) And IsFree and IsKeepOut vs ((IsTrack Or IsArc) And Not InPoly) And IsFree and IsKeepOut] p1: gap=0 ignorepadtopadclearanceinfootprint=FALSE
Clearance Clearance_BoardEdge_MountingHoles [OnCopper and InComponentClass('Mounting Holes') vs IsKeepOut] p2: gap=25 ignorepadtopadclearanceinfootprint=FALSE except(0: Arc-Hole Track-Hole SMDPad-Hole THPad-Hole Via-Hole Fill-Hole Poly-Hole Region-Hole Text-Hole)
Clearance Clearance_BoardEdge_Poly [OnCopper and InPoly vs IsKeepOut] p3: gap=10 ignorepadtopadclearanceinfootprint=FALSE
Clearance Clearance_BoardEdge [OnCopper and Not InComponentClass('Logo') and not InComponentClass('FiducialMark') and Not IsKeepout vs IsKeepOut] p4: gap=10 ignorepadtopadclearanceinfootprint=FALSE
Clearance Clearance_Poly [InPolygon] p5: gap=5 ignorepadtopadclearanceinfootprint=FALSE except(0: Arc-Hole Track-Hole SMDPad-Hole THPad-Hole Via-Hole Fill-Hole Poly-Hole Region-Hole Text-Hole; 7.85: THPad-THPad; 8: THPad-Fill THPad-Poly THPad-Region)
Clearance [All] p6: gap=3 ignorepadtopadclearanceinfootprint=FALSE except(0: Arc-Hole Track-Hole SMDPad-Hole THPad-Hole Via-Hole Fill-Hole Poly-Hole Region-Hole Text-Hole; 7.85: Arc-THPad Track-THPad SMDPad-THPad THPad-THPad THPad-Via; 8: THPad-Fill THPad-Poly THPad-Region)
ComponentClearance ComponentClearance_3 [InComponentClass('SHUNT') vs InComponentClass('SHUNT')] p1: gap=0 collisioncheckmode=3 verticalgap=0 showdistances=FALSE
ComponentClearance ComponentClearance_2 [IsThruComponent vs InComponentClass('Outside Board Components')] p2: gap=8 collisioncheckmode=3 verticalgap=10 showdistances=FALSE
ComponentClearance ComponentClearance_1 [InComponentClass('Header') vs InComponentClass('SHUNT')] p3: gap=0 collisioncheckmode=3 verticalgap=0 showdistances=FALSE
ComponentClearance ComponentClearance_MountingHoles_FiducialMarks [InComponentClass('Mounting Holes') vs InComponentClass('FiducialMark')] p4: gap=50 collisioncheckmode=3 verticalgap=10 showdistances=FALSE
ComponentClearance ComponentClearance_Logo [InComponentClass('Logo')] p5: gap=50 collisioncheckmode=3 verticalgap=10 showdistances=FALSE
ComponentClearance ComponentClearance_ScrewToNut [(HasFootprint('NY PMS 440 0025 PH')) vs (HasFootprint('Keystone_1902C'))] p6: gap=5 collisioncheckmode=3 verticalgap=10 showdistances=FALSE
ComponentClearance ComponentClearance_MountingHoles [InComponentClass('Mounting Holes')] p7: gap=250 collisioncheckmode=3 verticalgap=100000 showdistances=FALSE
ComponentClearance ComponentClearance_SmallPassives [HasFootprint('0201*') or HasFootprint('0402*') or HasFootprint('0508') or HasFootprint('0603*') or HasFootprint('0612') or HasFootprint('0805*') or HasFootprint('0815*') or HasFootprint('0830*') or HasFootprint('1206*') or HasFootprint('1210*') or HasFootprint('1808*') or HasFootprint('1812*') or HasFootprint('1825*') or HasFootprint('2010*') or HasFootprint('2220*') or HasFootprint('2225*') or HasFootprint('2512*') or HasFootprint('2728*') or HasFootprint('3518*') vs HasFootprint('0201*') or HasFootprint('0402*') or HasFootprint('0508') or HasFootprint('0603*') or HasFootprint('0612') or HasFootprint('0805*') or HasFootprint('0815*') or HasFootprint('0830*') or HasFootprint('1206*') or HasFootprint('1210*') or HasFootprint('1808*') or HasFootprint('1812*') or HasFootprint('1825*') or HasFootprint('2010*') or HasFootprint('2220*') or HasFootprint('2225*') or HasFootprint('2512*') or HasFootprint('2728*') or HasFootprint('3518*')] p8: gap=10 collisioncheckmode=3 verticalgap=10 showdistances=FALSE
ComponentClearance ComponentClearance_THtoSMT [IsThruComponent vs IsSMTComponent] p9: gap=10 collisioncheckmode=3 verticalgap=30 showdistances=FALSE
ComponentClearance ComponentClearance_THtoTH [IsThruComponent vs IsThruComponent] p10: gap=10 collisioncheckmode=3 verticalgap=30 showdistances=FALSE
ComponentClearance [All] p11: gap=9 collisioncheckmode=3 verticalgap=10 showdistances=FALSE
DiffPairsRouting 100DiffZ [InDifferentialPair('AUX') Or InDifferentialPair('C_SBU') Or InDifferentialPair('SBU_6') Or InDifferentialPair('B_AUX_8') or InDifferentialPair('SBU_PA') or InDifferentialPair('SBU_PB') or InDifferentialPair('AUX_PA_SS') or InDifferentialPair('AUX_PB_SS') or InDifferentialPair('DPC_AUX') or InDifferentialPair('SS_AUX_PA_SS') or InDifferentialPair('SS_AUX_PB_SS') or InDifferentialPair('C_SBU_PA') or InDifferentialPair('C_SBU_PB')] p1: maxlimit=10 minlimit=4 mostfreqgap=10 toplayer_maxgap=6.5 toplayer_prefgap=6.5 toplayer_minwidth=4 toplayer_maxwidth=5 toplayer_prefwidth=5 midlayer1_maxgap=7 midlayer1_prefgap=7 midlayer1_minwidth=4 midlayer1_maxwidth=5 midlayer1_prefwidth=5 midlayer2_mingap=10 midlayer2_minwidth=15 midlayer2_maxwidth=15 midlayer2_prefwidth=15 midlayer3_mingap=10 midlayer3_minwidth=15 midlayer3_maxwidth=15 midlayer3_prefwidth=15 bottomlayer_maxgap=6.5 bottomlayer_prefgap=6.5 bottomlayer_minwidth=4 bottomlayer_maxwidth=5 bottomlayer_prefwidth=5 maxuncoupledlength=500
DiffPairsRouting 90DiffZ [InDifferentialPair('U_USB') or InDifferentialPair('C_USB_PA') or InDifferentialPair('C_USB_PB') or InDifferentialPair('F_USB_D')] p2: maxlimit=6 minlimit=4 mostfreqgap=5 toplayer_maxgap=5.5 toplayer_prefgap=5.5 toplayer_minwidth=4 toplayer_maxwidth=6 toplayer_prefwidth=6 midlayer1_prefgap=6 midlayer1_minwidth=4 midlayer1_maxwidth=6 midlayer1_prefwidth=6 midlayer2_mingap=5 midlayer2_maxgap=5 midlayer2_minwidth=5 midlayer2_maxwidth=5 midlayer2_prefwidth=5 midlayer3_mingap=5 midlayer3_maxgap=5 midlayer3_minwidth=5 midlayer3_maxwidth=5 midlayer3_prefwidth=5 bottomlayer_maxgap=5.5 bottomlayer_prefgap=5.5 bottomlayer_minwidth=4 bottomlayer_maxwidth=6 bottomlayer_prefwidth=6 maxuncoupledlength=1000
DiffPairsRouting 85DiffZ [InDifferentialPair('C_SSRX1_PA_SS') or InDifferentialPair('C_SSRX1_PB_SS') or InDifferentialPair('C_SSRX2_PA_SS') or InDifferentialPair('C_SSRX2_PB_SS') or InDifferentialPair('C_SSTX1_PA_SS') or InDifferentialPair('C_SSTX1_PB_SS') or InDifferentialPair('C_SSTX2_PA_SS') or InDifferentialPair('MX_SSRX_PA_SS') or InDifferentialPair('MX_SSRX_PB_SS') or InDifferentialPair('MX_SSTX_PA_SS') or InDifferentialPair('MX_SSTX_PB_SS') or InDifferentialPair('SSTX1_PA_SS') or InDifferentialPair('SSTX1_PB_SS') or InDifferentialPair('SSTX2_PA_SS') or InDifferentialPair('SSTX2_PB_SS') or InDifferentialPair('C_SSTX2_PB_SS') or InDifferentialPair('ML0') or InDifferentialPair('ML1') or InDifferentialPair('ML2') or InDifferentialPair('ML3') or InDifferentialPair('LNA_PA_SS') or InDifferentialPair('LNA_PB_SS') or InDifferentialPair('LNB_PA_SS') or InDifferentialPair('LNB_PB_SS') or InDifferentialPair('LNC_PA_SS') or InDifferentialPair('LNC_PB_SS') or InDifferentialPair('LND_PA_SS') or InDifferentialPair('LND_PB_SS') or InDifferentialPair('PA_SSRX') or InDifferentialPair('PA_SSTX') or InDifferentialPair('PB_SSRX') or InDifferentialPair('PB_SSTX') or InDifferentialPair('UC_SSTX') or InDifferentialPair('U_SSRX') or InDifferentialPair('U_SSTX') or InDifferentialPair('B_ML0') or InDifferentialPair('B_ML1') or InDifferentialPair('B_ML2') or InDifferentialPair('B_ML3') or InDifferentialPair('C_ML0') or InDifferentialPair('C_ML1') or InDifferentialPair('C_ML2') or InDifferentialPair('C_ML3')] p3: maxlimit=6 minlimit=4 mostfreqgap=5 toplayer_maxgap=5 toplayer_minwidth=4 toplayer_maxwidth=6.5 toplayer_prefwidth=6.5 midlayer1_prefgap=6 midlayer1_minwidth=4 midlayer1_maxwidth=7 midlayer1_prefwidth=7 midlayer2_mingap=5 midlayer2_maxgap=5 midlayer2_minwidth=5 midlayer2_maxwidth=5 midlayer2_prefwidth=5 midlayer3_mingap=5 midlayer3_maxgap=5 midlayer3_minwidth=5 midlayer3_maxwidth=5 midlayer3_prefwidth=5 bottomlayer_maxgap=5 bottomlayer_minwidth=4 bottomlayer_maxwidth=6.5 bottomlayer_prefwidth=6.5 maxuncoupledlength=1000
FabricationTestPointUsage TestPointUsage [All] p1: valid=2 allowmultiple=FALSE
FabricationTestpoint Testpoint [All] p1: side=3 testpointundercomponent=TRUE minsize=40 maxsize=100 preferedsize=60 minholesize=0 maxholesize=40 preferedholesize=32 testpointgrid=1 allowsidetop=TRUE allowsidebottom=TRUE usegrid=TRUE gridtolerance=0.01
FanoutControl Fanout_LCC [IsLCC] p1: bgadir=Out bgaviamode=Centered fanoutstyle=Auto fanoutdirection=Alternating viagrid=1 // Fanout_LCC (Default Rule)
FanoutControl Fanout_BGA [IsBGA] p2: bgadir=Out bgaviamode=Centered fanoutstyle=Auto fanoutdirection=Alternating viagrid=1 // Fanout_BGA (Default Rule)
FanoutControl Fanout_Default [All] p4: bgadir=Out bgaviamode=Centered fanoutstyle=Auto fanoutdirection=Alternating viagrid=1 // Fanout_Default (Default Rule)
FanoutControl Fanout_Small [(CompPinCount < 5)] p5: bgadir=Out bgaviamode=Centered fanoutstyle=Auto fanoutdirection=OutThenIn viagrid=1 // Fanout_Small (Default Rule)
HoleSize [All] p1: absolutevalues=TRUE maxlimit=251 minlimit=7 maxpercent=80.000 minpercent=20.000
HoleToHoleClearance HoleToHoleClearance_1 [HasFootprint('Lintes_20-0000016-01') vs HasFootprint('Lintes_20-0000016-01')] p1: gap=0 allowstackedmicrovias=TRUE
HoleToHoleClearance [All] p2: gap=10 allowstackedmicrovias=TRUE
MinimumAnnularRing MinimumAnnularRing_ThermalPadVias [IsVia and InAnyComponent] p1: minimumring=4
MinimumAnnularRing [All] p2: minimumring=2.9
MinimumSolderMaskSliver MinimumSolderMaskSliver_Logo [InComponentClass('Logo') vs InComponentClass('Logo')] p1: minsoldermaskwidth=3
MinimumSolderMaskSliver [All] p2: minsoldermaskwidth=3
PlaneClearance [All] p1: clearance=5
PlaneConnect [All] p1: planeconnectstyle=Direct reliefexpansion=10 reliefentries=4 reliefconductorwidth=10 reliefairgap=10
PolygonConnect [All] p1: connectstyle=Direct reliefconductorwidth=10 reliefentries=4 polygonreliefangle="90 Angle" airgapwidth=10
RoutingVias ThermalPadVias [IsVia and InAnyComponent] p1: holewidth=7.87 width=19.68 viastyle="Through Hole" minholewidth=6 minwidth=15 maxholewidth=12.99 maxwidth=23.62
RoutingVias [All] p2: holewidth=8 width=16 viastyle="Through Hole" minholewidth=7 minwidth=16 maxholewidth=40 maxwidth=65
SilkToBoardRegionClearance [Not ((IsComment or IsDesignator) And (Hide <> 'False')) and not InRegion(1000,500,4000,800)] p1:
SilkToSilkClearance SilkToSilkClearance_Pb-FreeLogo [(HasFootprint('Pb-Free_Overlay_Medium') OR HasFootprint('Pb-Free_Overlay_Small')) vs (HasFootprint('Pb-Free_Overlay_Medium') OR HasFootprint('Pb-Free_Overlay_Small'))] p1: silktosilkclearance=0
SilkToSilkClearance [All] p2: silktosilkclearance=4
SilkToSolderMaskClearance SilkToComonentPadClearance [IsPad and InAnycomponent] p1: minsilkscreentomaskgap=3 clearancetoexposedcopper=TRUE
SilkToSolderMaskClearance "Silk to Solder Mask Opening" [All] p2: minsilkscreentomaskgap=4 clearancetoexposedcopper=FALSE
SolderMaskExpansion [All] p1: expansion=0
Width [All] p1: maxlimit=100 minlimit=4 preferedwidth=10 minimp=50.000000 maximp=50.000000 favimp=50.000000 checkconnectedcopper=TRUE
13 further rules are at their usual default settings.

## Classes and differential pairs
component class "PSIL054E1_Sink PD Controller": C200 C201 C202 C203 C204 C205 C206 C207 C208 C209 C210 C211 C212 C213 D200 F200 J200 R200 R201 R202 R203 R204 R205 R206 R207 R208 R209 R210 R211 R212 U200 U201
component class PSIL054E1_FTDI: C214 C215 C216 C217 C218 C219 C220 C221 C222 C223 C224 C225 C226 C227 C228 C229 C230 C231 C232 D205 J201 J202 J203 L200 R225 R226 R227 R228 R229 R230 R231 R232 R233 R234 R235 R236 R237 R238 R239 R240 R241 R242 R243 R244 U202 U203 U204 U205 Y200
component class "PSIL054E1_Sink Buttons LEDs": D201 D202 D203 D204 Q200 Q201 Q202 Q203 R213 R214 R215 R216 R217 R218 R219 R220 R221 R222 R223 R224 S200 S201 S202 S203 TP200 TP201
component class "PSIL054E1_Source PD Controller": C18 C19 C20 C21 C22 C23 C24 C25 C26 D9 J2 R36 R37 R38 R39 R40 R41 R42 R43 R44 R45 R46 R47 R48 R49 R50 R51 R52 R53 R54 R55 R56 R57 R58 R59 R60 R61 R62 R63 R64 R65 R66 R67 S1 S2 S3 S4 U5 U6
component class "PSIL054E1_Bypass Power Path": C12 C13 C14 C15 C16 Q10 Q11 R22 R23 R24 R25 R26 R27 R31 R32
component class AssemblyNote: ZZ2 ZZ3 ZZ4
component class FiducialMark: FID1 FID2 FID3 FID4 FID5 FID6
component class PSIL054E1_EVM_Hardware: FID1 FID2 FID3 FID4 FID5 FID6 Logo200 Logo203 Logo? SH-J1 ZZ2 ZZ3 ZZ4
component class "PSIL054E1_Source Type-C Connector": C27 C28 C29 C30 C? D10 D? J3 R317 R318
component class Header: J2 J202
component class "PSIL054E1_Variable DCDC": C1 C2 C3 C4 C5 C6 C7 C8 C9 C10 C11 D1 D2 D3 D4 D5 D6 D7 D8 J1 L1 L2 Q1 Q2 Q3 Q4 Q5 Q6 Q7 Q8 Q9 R1 R2 R3 R4 R5 R6 R7 R8 R9 R10 R11 R12 R13 R14 R15 R16 R17 R18 R19 R20 R21 TP1 TP2 TP3 U1 U2 U3
component class Shunt: SH-J1
differential pair F_USB_D: +F_USB_D_P -F_USB_D_N
differential pair C_USB: +C_USB_P -C_USB_N

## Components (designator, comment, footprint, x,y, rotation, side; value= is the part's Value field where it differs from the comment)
C1 "TAJE476M035RNJ" 7343-43 1195,1408 r270 bottom value=47uF
C2 "TAJE476M035RNJ" 7343-43 1195.1,2316.26 r90 bottom value=47uF
C3 "C2012X5R1V226M125AC" 0805_HV 1504.66,871.41 r0 bottom value=22uF
C4 "C2012X5R1V226M125AC" 0805_HV 1504.66,791.41 r0 bottom value=22uF
C5 "C1005X7R1H104K050BB" 0402 1494.66,949.93 r0 bottom value=0.1uF
C6 "C1005X7R1H102M050BE" 0402 1374.66,809.93 r180 bottom value=1000pF
C7 "GMK105BJ104KV-F" 0402 1327.13,1406.68 r270 bottom value=0.1uF
C8 "CC0402KRX7R9BB101" 0402 1267,1092 r180 top value=100pF
C9 "C1005X7R1H102M050BE" 0402 1176.47,869.93 r0 bottom value=1000pF
C10 "C1005X5R1V225K050BC" 0402_065L 1299.66,1155.93 r0 top value=2.2uF
C11 "GRM21BR60J476ME15L" 0805_HV 1300.66,1494.93 r180 top value=47uF
C12 "C2012X5R1V226M125AC" 0805_HV 1854.66,1089.93 r180 bottom value=22uF
C13 "C2012X5R1V226M125AC" 0805_HV 1854.66,1009.93 r180 bottom value=22uF
C14 "GMK105BJ104KV-F" 0402 1854.66,1151.74 r180 bottom value=0.1uF
C15 "GRM155R71E104KE14D" 0402 1636.47,1126.15 r90 bottom value=0.1uF
C16 "GRM155R71E104KE14D" 0402 1677.66,1399.93 r270 bottom value=0.1uF
C18 "GRM033R71E221KA01D" 0201 1370.1,1835.26 r90 top value=220pF
C19 "GRM033R71E221KA01D" 0201 1370.1,1776.26 r270 top value=220pF
C20 "885012205037" 0402 1546.57,2619.01 r0 bottom value=0.1uF
C21 "UMK107AB7105KA-T" 0603 1367.57,2157.01 r180 top value=1uF
C22 "CL05A106MP5NUNC" 0402S 1547,1742 r90 bottom value=10uF
C23 "CL05A106MP5NUNC" 0402S 1551,2076 r90 bottom value=10uF
C24 "GRM188R61E106MA73D" 0603S 1681,2262 r90 bottom value=10uF
C25 "GRM188R61E106MA73D" 0603S 1475,2261 r90 bottom value=10uF
C26 "CL05A106MP5NUNC" 0402S 1593.1,2076.26 r90 bottom value=10uF
C27 "GRM155R71H103KA88D" 0402 1712.48,2222.26 r0 top value=0.01uF
C28 "GRM155R71H103KA88D" 0402 1712.48,2181.26 r0 top value=0.01uF
C29 "GRM155R71H103KA88D" 0402 1367,2099 r180 top value=0.01uF
C30 "GRM155R71H103KA88D" 0402 1713.38,2140 r0 top value=0.01uF
C200 "GRM188R61H105KAALD" 0603 564.45,1966.31 r90 bottom value=1uF
C201 "GRM188R61H105KAALD" 0603 389,1966 r90 bottom value=1uF
C202 "GCM155R71H104KE02D" 0402 421.45,2291.31 r180 top value=0.1uF
C203 "GCM155R71H104KE02D" 0402 589.45,2291.31 r0 top value=0.1uF
C204 "GCM155R71H104KE02D" 0402 584.45,2351.31 r0 bottom value=0.1uF
C205 "GCM155R71H104KE02D" 0402 419.45,2351.31 r180 bottom value=0.1uF
C206 "GRM155R61A106ME44" 0402_070 485.45,1513.31 r270 top value=10uF
C207 "GRM155R61A106ME44" 0402_070 513.45,1838.31 r0 bottom value=10uF
C208 "GRM033R61E104KE14J" 0201_033 512.45,1872.31 r0 bottom value=0.1uF
C209 "C2012X5R1V106K085AC" 0805_HV 633,1966 r90 bottom value=10uF
C210 "C2012X5R1V106K085AC" 0805_HV 456,1966 r90 bottom value=10uF
C211 "GRM033R71E221KA01D" 0201 323.45,1617.31 r90 top value=220pF
C212 "GRM033R71E221KA01D" 0201 323.45,1675.31 r270 top value=220pF
C213 "GRM033R61E104KE14J" 0201_033 252.44,1866.31 r0 bottom value=0.1uF
C214 "C1005X7R1H104K050BB" 0402 564.45,956.31 r90 top value=0.1uF
C215 "C1005X5R1A475M050BC" 0402 524.45,956.31 r90 top value=4.7uF
C216 "C1005X7R1H104K050BB" 0402L 584,1359 r180 bottom value=0.1uF
C217 "C1005X7R1H104K050BB" 0402 469.45,956.31 r270 top value=0.1uF
C218 "C1005X5R1A475M050BC" 0402 429.45,956.31 r270 top value=4.7uF
C219 "C1005X7R1H104K050BB" 0402 701.45,858.31 r0 bottom value=0.1uF
C220 "C1005X7R1H104K050BB" 0402 390.45,1148.31 r270 top value=0.1uF
C221 "C1005X7R1H104K050BB" 0402 389.45,956.31 r90 top value=0.1uF
C222 "C1005X7R1H104K050BB" 0402 556.45,1059.31 r180 top value=0.1uF
C223 "C1005X7R1H104K050BB" 0402 488.45,1148.31 r270 top value=0.1uF
C224 "C1005X7R1H104K050BB" 0402 333.45,1149.31 r270 top value=0.1uF
C225 "C1005X7R1H104K050BB" 0402 334.45,985.31 r90 top value=0.1uF
C226 "C1005X5R1A475M050BC" 0402 701.45,1240.31 r0 bottom value=4.7uF
C227 "CL10C270FB8NNNC" 0603 619.45,726.31 r180 bottom value=27pF
C228 "C0402C103J5RACTU" 0402 415.45,245.31 r180 bottom value=0.01uF
C229 "CL10C270FB8NNNC" 0603 484.45,726.31 r0 bottom value=27pF
C230 "C1005X7R1H104K050BB" 0402 74.45,111.31 r0 bottom value=0.1uF
C231 "C2012X5R1V106K085AC" 0805_HV 98,596 r0 bottom value=10uF
C232 "293D106X9010B2TE3" 3528-21 119,492 r0 bottom value=10uF
D1 "PMEG4050EP,115" SOD-128 1314.66,994.93 r270 bottom value=40V
D2 "LTST-C193TBKT-5A" LTST-C193_Blue 1927,567 r90 top value=Blue
D3 "150060GS75000" WL-SMCW_GREEN 1122.66,1172.93 r270 top value=Green
D4 "PESD24VS2UT,215" SOT-23 1946,221 r270 bottom value=24V
D5 "LW QH8G-Q2S2-3K5L-1" "LW QH8G_White" 1858.44,1678.26 r180 top value=White
D6 "LW QH8G-Q2S2-3K5L-1" "LW QH8G_White" 1858.44,1778.26 r180 top value=White
D7 "LW QH8G-Q2S2-3K5L-1" "LW QH8G_White" 1858.44,1878.26 r180 top value=White
D8 "LW QH8G-Q2S2-3K5L-1" "LW QH8G_White" 1858.44,1978.26 r180 top value=White
D9 "LW QH8G-Q2S2-3K5L-1" "LW QH8G_White" 1791.38,2207 r90 top value=White
D10 "NSR20F30NXT5G" DSN2_0603 1359.57,2221.01 r180 top value=30V
D200 "LW QH8G-Q2S2-3K5L-1" "LW QH8G_White" 874.45,2501.31 r270 top value=White
D201 "LW QH8G-Q2S2-3K5L-1" "LW QH8G_White" 874.45,2101.31 r270 top value=White
D202 "LW QH8G-Q2S2-3K5L-1" "LW QH8G_White" 874.45,1701.31 r270 top value=White
D203 "LW QH8G-Q2S2-3K5L-1" "LW QH8G_White" 874.45,1296.31 r270 top value=White
D204 "LW QH8G-Q2S2-3K5L-1" "LW QH8G_White" 874.45,901.31 r270 top value=White
D205 "LW QH8G-Q2S2-3K5L-1" "LW QH8G_White" 504.45,116.31 r0 top value=White
F200 "SSQ 15" FUSE_SSQ 509.45,2531.31 r180 bottom
FID1 "Fiducial" Fiducial10-20#1 1107,2643 r0 top
FID2 "Fiducial" Fiducial10-20#2 2012,70 r180 top
FID3 "Fiducial" Fiducial10-20#2 2023,2645 r0 top
FID4 "Fiducial" Fiducial10-20#2 1977,90 r180 bottom
FID5 "Fiducial" Fiducial10-20#2 1190,90 r180 bottom
FID6 "Fiducial" Fiducial10-20#2 1190,2618 r180 bottom
J1 "JPD113D-LBA21-7H" Foxconn_JPD113D-LBA21 1563.5,-0.07 r0 top
J2 "SSQ-104-03-G-D" Samtec_SSQ-104-03-x-D 1154,1859 r90 bottom
J3 "632723300011" Wurth_632_723_300_011 1563.5,2697.68 r180 top
J200 "632723300011" Wurth_632_723_300_011 504.45,2761.31 r180 top
J201 "ZX62RD-AB-5P8" Hirose_ZX62RD-AB-5P8 504.45,56.31 r180 bottom
J202 "TSW-103-07-G-S" TSW-103-07-G-S 939.45,156.31 r270 top
J203 "SSQ-104-03-G-D" Samtec_SSQ-104-03-x-D 889.45,526.31 r270 bottom
L1 "ASPI-0630LR-100M-T15" ASPI-0630LR 1512.13,1381.68 r90 bottom value=10uH
L2 "74437324100" WE-LHMI_4020 1288.66,1367.93 r0 top value=10uH
L200 "BLM18SG260TN1D" 0603 408.45,303.31 r180 bottom value="26 ohm"
Logo200 "CE Mark" CE_Mark_5mm 1891,2228 r90 bottom
Logo203 "WEEE logo" WEEE_Minimum 1589,1904 r90 bottom
Logo? "FCC disclaimer" FCC_disclaimer 2156.07,688 r90 bottom
Q1 "AON7403" TRANS_AOS_DFN3X3 1494.66,1049.93 r0 bottom value=-30V
Q2 "BSH105,215" SOT-23 1218.66,688.93 r90 top value=20V
Q3 "BSH105,215" SOT-23 1218.66,840.93 r90 top value=20V
Q4 "BSH105,215" SOT-23 1218.66,992.93 r90 top value=20V
Q5 "NX3020NAKW,115" SOT-323 1172.66,1175.93 r180 bottom value=30V
Q6 "NX3020NAKW,115" SOT-323 1873.1,1679.26 r0 bottom value=30V
Q7 "NX3020NAKW,115" SOT-323 1872.1,1778.26 r0 bottom value=30V
Q8 "NX3020NAKW,115" SOT-323 1870.1,1878.26 r0 bottom value=30V
Q9 "NX3020NAKW,115" SOT-323 1870.1,1978.26 r0 bottom value=30V
Q10 "SI7997DP-T1-GE3" "PowerPAK_SO-8 _Dual" 1847.66,1389.93 r90 bottom value=-30V
Q11 "NX3008NBKW,115" SOT-323 1664.66,929.93 r180 bottom value=30V
Q200 "BSS138W-7-F" SOT-323 809.45,2011.31 r0 bottom value=50V
Q201 "BSS138W-7-F" SOT-323 809.45,1611.31 r0 bottom value=50V
Q202 "BSS138W-7-F" SOT-323 809.45,1206.31 r0 bottom value=50V
Q203 "BSS138W-7-F" SOT-323 809.45,811.31 r0 bottom value=50V
R1 "ERJ-6GEY0R00V" 0805_HV 1644.66,679.93 r0 top value=0
R2 "CRCW0402100KFKED" 0402 1504.66,669.93 r0 top value=100k
R3 "CRCW040247K5FKED" 0402 1374.66,849.93 r0 bottom value=47.5k
R4 "CRCW040230K0JNED" 0402 1171,1092 r180 top value=30k
R5 "CRCW0402100KFKED" 0402 1113,596.79 r90 bottom value=100k
R6 "CRCW0402270RJNED" 0402 1194.66,679.93 r0 bottom value=270
R7 "RC0603JR-0710KL" 0603L 1864.66,569.93 r90 top value=10k
R8 "ERJ-2RKF1002X" 0402 1083.66,1174.93 r90 bottom value=10.0k
R9 "CRCW040211K0FKED" 0402 1113,500.79 r90 bottom value=11.0k
R10 "CRCW04029K53FKED" 0402 1176.47,909.93 r180 bottom value=9.53k
R11 "CRCW0402100KFKED" 0402 1126.66,688.93 r270 top value=100k
R12 "CRCW0402100KFKED" 0402 1126.66,840.93 r270 top value=100k
R13 "CRCW0402100KFKED" 0402 1126.66,992.93 r270 top value=100k
R14 "CRCW04028K87FKED" 0402 1310.66,688.93 r270 top value=8.87k
R15 "CRCW04023K65FKED" 0402 1310.66,840.93 r270 top value=3.65k
R16 "CRCW04022K20FKED" 0402 1310.66,992.93 r270 top value=2.20k
R17 "CRCW0402100KFKED" 0402 1401.66,1260.93 r90 top value=100k
R18 "ERJ-2RKF1002X" 0402L 1857.1,1635.26 r180 top value=10.0k
R19 "ERJ-2RKF1002X" 0402L 1857.1,1734.26 r180 top value=10.0k
R20 "ERJ-2RKF1002X" 0402L 1856.1,1833.26 r180 top value=10.0k
R21 "ERJ-2RKF1002X" 0402L 1856.44,1934.26 r180 top value=10.0k
R22 "CRCW20100000Z0EF" 2010 2006.66,839.93 r90 bottom value=0
R23 "CRCW20100000Z0EF" 2010 1675.13,1636.68 r180 bottom value=0
R24 "ERJ-2RKF1002X" 0402 1854.66,1191.74 r0 bottom value=10.0k
R25 "ERJ-2RKF1002X" 0402 1676.47,1126.15 r270 bottom value=10.0k
R26 "ERJ-2RKF1002X" 0402 1717.66,1399.93 r90 bottom value=10.0k
R27 "ERJ-2RKF1002X" 0402 1644.66,1029.93 r90 bottom value=10.0k
R31 "ERJ-2RKF1001X" 0402 1685.66,1029.93 r90 bottom value=1.00k
R32 "CRCW0402100KFKED" 0402 1726.66,1029.93 r270 bottom value=100k
R36 "CRCW04023K83FKED" 0402 1326,1741 r90 top value=3.83k
R37 "CRCW04023K83FKED" 0402 1367.29,1652.26 r270 top value=3.83k
R38 "ERJ-2RKF1002X" 0402 1408.29,1652.26 r270 top value=10.0k
R39 "CRCW04023K30JNED" 0402 1780,2586 r270 bottom value=3.3k
R40 "CRCW04023K30JNED" 0402 1627.57,2646.01 r270 bottom value=3.3k
R41 "CRCW04023K30JNED" 0402 1323.57,2538.01 r90 bottom value=3.3k
R42 "CRCW04023K30JNED" 0402 1780,2479 r270 bottom value=3.3k
R43 "RC0402JR-070RL" 0402L 1677.57,2644.01 r270 bottom value=0
R44 "ERJ-2RKF1002X" 0402 1531.29,1652.26 r90 top value=10.0k
R45 "CRCW04023K83FKED" 0402 1490.29,1652.26 r90 top value=3.83k
R46 "CRCW04023K83FKED" 0402 1449.29,1652.26 r90 top value=3.83k
R47 "CRCW020110K0FKED" 0201 1739,2045 r270 bottom value=10.0k
R48 "CRCW02010000Z0ED" 0201 1285,1607 r90 top value=0
R49 "CRCW02010000Z0ED" 0201 1316.57,1640.01 r90 top value=0
R50 "CRCW02010000Z0ED" 0201 1284.57,1725.01 r270 top value=0
R51 "CRCW02010000Z0ED" 0201 1284.57,1666.01 r90 top value=0
R52 "CRCW0201100KFKED" 0201 1739.1,2109.32 r270 bottom value=100k
R53 "CRCW02010000Z0ED" 0201 1284.57,1784.01 r270 top value=0
R54 "CRCW02010000Z0ED" 0201 1284.57,1961.01 r270 top value=0
R55 "CRCW02010000Z0ED" 0201 1284.57,1902.01 r90 top value=0
R56 "CRCW02010000Z0ED" 0201 1284.57,2028.01 r90 top value=0
R57 "CRCW02010000Z0ED" 0201 1284.57,1843.01 r270 top value=0
R58 "CRCW04020000Z0EDHP" 0402 1739.13,1635.68 r0 top value=0
R59 "CRCW0402100KDHEDP" 0402 1610.66,1423.93 r0 top value=100k
R60 "CRCW04020000Z0EDHP" 0402 1867.66,1423.93 r0 top value=0
R61 "ERJ-2RKF1002X" 0402L 1791.38,2132 r270 top value=10.0k
R62 "CRCW0402100KDHEDP" 0402 1610.66,1205.93 r0 top value=100k
R63 "CRCW04020000Z0EDHP" 0402 1867.66,1205.93 r0 top value=0
R64 "CRCW0402100KDHEDP" 0402 1610.66,983.93 r0 top value=100k
R65 "CRCW04020000Z0EDHP" 0402 1867.66,983.93 r0 top value=0
R66 "CRCW0402100KDHEDP" 0402 1866.66,770.93 r0 top value=100k
R200 "TNPW060310K0BEEA" TNPW0603 809.45,2581.31 r180 bottom value=10.0k
R201 "CRCW02013K83FKED" 0201 334.45,1501.31 r180 top value=3.83k
R202 "CRCW02013K83FKED" 0201 389.45,1501.31 r0 top value=3.83k
R203 "CRCW02013K83FKED" 0201 441,1508 r0 top value=3.83k
R204 "CRCW02013K83FKED" 0201 433.45,1534.31 r0 top value=3.83k
R205 "RC0201FR-073K32L" 0201 751.45,169.32 r90 bottom value=3.32k
R206 "RC0201FR-073K32L" 0201 184.45,1526.31 r270 bottom value=3.32k
R207 "RC0201FR-073K32L" 0201 184.45,1881.31 r90 bottom value=3.32k
R208 "RC0201FR-073K32L" 0201 134.45,1526.31 r270 bottom value=3.32k
R209 "RC0201FR-07191KL" 0201 466.45,2084.31 r180 bottom value=191k
R210 "MCR006YRTF1002" 0201 566.45,2084.31 r0 bottom value=10.0k
R211 "RC0201FR-7D100KL" 0201 466.45,2060.31 r0 bottom value=100k
R212 "RC0201FR-7D100KL" 0201 566.45,2060.31 r180 bottom value=100k
R213 "TNPW060310K0BEEA" TNPW0603 809.45,2181.31 r180 bottom value=10.0k
R214 "TNPW060310K0BEEA" TNPW0603 809.45,1781.31 r180 bottom value=10.0k
R215 "CRCW04020000Z0EDHP" 0402 139.45,2546.31 r0 top value=0
R216 "CRCW0402100KDHEDP" 0402 139.45,2161.31 r180 top value=100k
R217 "CRCW04020000Z0EDHP" 0402 139.45,2111.31 r0 top value=0
R218 "CRCW0402100KDHEDP" 0402 139.45,1726.31 r180 top value=100k
R219 "CRCW04020000Z0EDHP" 0402 139.45,1676.31 r0 top value=0
R220 "TNPW060310K0BEEA" TNPW0603 809.45,1376.31 r180 bottom value=10.0k
R221 "TNPW060310K0BEEA" TNPW0603 809.45,981.31 r180 bottom value=10.0k
R222 "CRCW0402100KDHEDP" 0402 139.45,1291.31 r180 top value=100k
R223 "CRCW04020000Z0EDHP" 0402 139.45,1241.31 r0 top value=0
R224 "CRCW0402100KDHEDP" 0402 139.45,861.31 r180 top value=100k
R225 "ERJ-2RKF1002X" 0402 764.45,1512.31 r0 bottom value=10.0k
R226 "ERJ-2RKF1002X" 0402 636,1399 r180 bottom value=10.0k
R227 "ERJ-2RKF1002X" 0402 764.45,1471.31 r0 bottom value=10.0k
R228 "RC0402FR-072K2L" 0402 643.45,1601.31 r0 bottom value=2.20k
R229 "CRCW040212K0JNED" 0402 239.45,826.31 r180 bottom value=12k
R230 "ERJ-2RKF4701X" 0402 314.45,456.31 r270 bottom value=4.70k
R231 "CRCW04020000Z0ED" 0402 344.45,681.31 r270 bottom value=0
R232 "ERJ-2RKF1001X" 0402 329.45,531.31 r180 bottom value=1.00k
R233 "CRCW04020000Z0ED" 0402 459.45,1059.31 r180 top value=0
R234 "ERJ-2RKF1002X" 0402 504.45,66.31 r0 top value=10.0k
R235 "ERJ-2RKF1002X" 0402 354.45,456.31 r90 bottom value=10.0k
R236 "CRCW04020000Z0ED" 0402 370.45,1366.31 r90 bottom value=0
R237 "CRCW04020000Z0ED" 0402 94.45,991.31 r180 bottom value=0
R238 "CRCW04020000Z0ED" 0402 94.45,1031.31 r180 bottom value=0
R239 "CRCW04020000Z0ED" 0402 94.45,1071.31 r180 bottom value=0
R240 "CRCW04020000Z0ED" 0402 822.45,156.31 r180 bottom value=0
R241 "CRCW04020000Z0ED" 0402 104.45,1206.31 r90 bottom value=0
R242 "CRCW0603249KFKEA" 0603 259.45,421.31 r90 bottom value=249k
R243 "CRCW04020000Z0ED" 0402 144.45,1206.31 r90 bottom value=0
R244 "CRCW04020000Z0ED" 0402 174.45,111.31 r0 bottom value=0
S1 "434121025816" SW_434121025816 1738.66,1533.93 r180 top
S2 "434121025816" SW_434121025816 1738.66,1313.93 r180 top
S3 "434121025816" SW_434121025816 1738.66,1093.93 r180 top
S4 "434121025816" SW_434121025816 1738.66,873.93 r180 top
S200 "434121025816" SW_434121025816 114.45,2351.31 r90 top
S201 "434121025816" SW_434121025816 114.45,1921.31 r90 top
S202 "434121025816" SW_434121025816 114.45,1481.31 r90 top
S203 "434121025816" SW_434121025816 114.45,1051.31 r90 top
SH-J1 "60900213421" Wurth_60900213421 940,209 r90 top
TP1 "TESTPOINT" Keystone_5019 1904.66,249.93 r90 top
TP2 "TESTPOINT" Keystone_5019 1204.66,249.93 r90 top
TP3 "TESTPOINT" Keystone_5019 1123,1489 r270 top
TP200 "5019" Keystone_5019 636,376 r0 top
TP201 "5019" Keystone_5019 372,376 r0 top
U1 "TVS2200DRVR" DRV0006A 1626.66,815.93 r270 bottom
U2 "LM3489QMM/NOPB" MUA08A_N 1194.66,769.93 r0 bottom
U3 "TPS62177DQCR" DQC0010A 1289.66,1224.93 r90 top
U5 "TPS65987DDHRSHR" RSH0056E_NSMD 1563.5,1860.26 r270 top
U6 "MX25L8006EM1I-12G" SOP-8_150MIL 1563,2488 r180 bottom
U200 "TPS65987DDHRSHR" RSH0056E 504.45,1701.31 r270 top
U201 "MX25L8006EM1I-12G" SOP-8_150MIL 159.45,1701.31 r90 bottom
U202 "93LC56B-I/OT" SOT-23-6 644.45,1497.31 r270 bottom
U203 "FT4232HL" LQFP64_N 459.45,1048.98 r90 bottom
U204 "TPD2E009DRTR" DRT0003A 502.45,308.31 r90 bottom
U205 "TPS76833QD" D0008A_N 124.45,281.31 r90 bottom
Y200 "ECS-120-20-3X-TR" ECS_CSM-3X 534.45,591.31 r180 bottom
ZZ2 "These assemblies are ESD sensitive, ESD precautions shall be observed." AssemblyNote 185,3829.11 r0 top
ZZ3 "These assemblies must be clean and free from flux and all contaminants. Use of no clean flux is not acceptable." AssemblyNote 185,3740.56 r0 top
ZZ4 "These assemblies must comply with workmanship standards IPC-A-610 Class 2, unless otherwise specified." AssemblyNote 185,3652 r0 top

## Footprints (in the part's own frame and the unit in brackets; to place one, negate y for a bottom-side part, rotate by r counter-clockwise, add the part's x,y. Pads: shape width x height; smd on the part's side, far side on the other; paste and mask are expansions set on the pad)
0201 [mm] "Data from Kemet datasheet CC101_COM dated 7/28/11"
  rect 0.46x0.42 smd mask+0.048: 1(-0.33,0) 2(0.33,0)
  body extent -0.31,-0.16 0.31,0.16, height 0.26
0201_033 [mm] "SMD, 2-Leads, Height 0.33mm"
  rect 0.46x0.42 smd mask+0.048: 1(-0.33,0) 2(0.33,0)
  body extent -0.31,-0.16 0.31,0.16, height 0.33
0402 [mm] "0402 from SM-752 data"
  rect 0.8x0.6 smd: 1(-0.6,0) 2(0.6,0)
  silkscreen extent -1.22,-0.52 1.22,0.52, body extent -0.55,-0.3 0.55,0.3, height 0.6
0402_065L [mm] "0402"
  rect 0.6x0.5 smd: 1(-0.5,0) 2(0.5,0)
  body extent -0.55,-0.3 0.55,0.3, height 0.65
0402_070 [mil] "SMD, 2-Leads, Body 1.2x0.7mm, Height 0.7mm"
  rect 15x24 smd: 1(-20,0) 2(20,0)
  body extent -24,-14 24,14, height 28
0402L [mm] "0402 from SM-752 data"
  rect 0.6x0.5 smd: 1(-0.5,0) 2(0.5,0)
  body extent -0.55,-0.3 0.55,0.3, height 0.6
0402S [mil] "Based on C0402S footprint from PADS legacy"
  rect 15x24 smd: 1(-20,0) 2(20,0)
  body extent -22,-12 22,12, height 24
0603 [mm] "0603 from SM-752 data"
  rect 1x0.95 smd: 1(-0.8,0) 2(0.8,0)
  silkscreen extent -1.52,-0.69 1.52,0.69, body extent -0.87,-0.47 0.87,0.47, height 1
0603L [mm] "0603 from SM-752 data"
  rect 0.8x0.85 smd: 1(-0.7,0) 2(0.7,0)
  silkscreen extent -0.07,-0.33 0.07,0.33, body extent -0.87,-0.47 0.87,0.47, height 1
0603S [mil]
  rect 20x35 smd: 1(-30,0) 2(30,0)
  silkscreen extent -10,-17 10,17, body extent -34,-19 34,19, height 39
0805_HV [mil] "0805 with 30mil clearance between pads"
  rect 50x63 smd: 1(-40,0) 2(40,0)
  silkscreen extent -74,-40 74,40, body extent -43,-29 43,29, height 57
2010 [mm] "Chip Capacitor, Body 5.08x2.54mm, IPC Medium Density"
  rect 1.6x2.7 smd: 1(-2.3,0) 2(2.3,0)
  silkscreen extent -3.42,-1.65 3.42,1.65, body extent -2.73,-1.45 2.73,1.45, height 1.66
3528-21 [mm] "Medium Density IPC, based on Kemet datasheet 2016-10-20"
  rrect6% 1.8x2.23 smd: 1(-1.46,0) 2(1.46,0)
  silkscreen extent -2.29,-1.5 0.76,1.5, body extent -1.85,-1.5 1.85,1.5, height 2.12
7343-43 [mm] "Medium density IPC based on Kemet T495 series"
  rect 2.55x2.45 smd: 1(-3.025,0) 2(3.025,0)
  silkscreen extent -4.56,-2.3 3.8,2.3, body extent -3.8,-2.3 3.8,2.3, height 4.3
ASPI-0630LR [mm] "SMD, 2-Leads, Body 7.2x6.65mm"
  rect 2.35x3.4 smd: 1(-3.025,0) 2(3.025,0)
  silkscreen extent -3.75,-3.42 3.75,3.42, body extent -3.75,-3.42 3.75,3.42, height 3
AssemblyNote [mil] "Assembly Note"
CE_Mark_5mm [mil] "Minimum text height for CE Mark"
  silkscreen extent -138,-98 138,98
D0008A_N [mm] "SOIC, 8-Leads, Body 4.9x3.9mm, Pitch 1.27mm, IPC Medium Density"
  oval 1.45x0.6 smd: 1(-2.725,1.905) 2(-2.725,0.635) 3(-2.725,-0.635) 4(-2.725,-1.905) 5(2.725,-1.905) 6(2.725,-0.635) 7(2.725,0.635) 8(2.725,1.905)
  silkscreen extent -3.3,-2.5 0.9,2.5, body extent -3,-2.45 3,2.45, height 1.63
DQC0010A [mm] "SON, 10-Leads, Body 2x3mm, Pitch 0.5mm, Thermal Pad 2.4x0.84mm"
  rrect40% 0.5x0.25 smd: 1(-0.95,1) 2(-0.95,0.5) 3(-0.95,0) 4(-0.95,-0.5) 5(-0.95,-1) 6(0.95,-1) 7(0.95,-0.5) 8(0.95,0) 9(0.95,0.5) 10(0.95,1)
  rrect12% 0.8x1.08 on Top Paste: 11(0,0.64) 11(0,-0.64)
  rrect12% 0.84x2.4 smd paste-0.42: 11(0,0)
  silkscreen extent -1.18,-1.68 1.17,1.68, body extent -1,-1.5 1,1.5, height 0.77
DRT0003A [mm] "SOTFL, 3-Leads, Body 1x1mm (inc leads), Pitch 0.35mm"
  rect 0.45x0.3 smd: 1(-0.575,0.35) 2(-0.575,-0.35) 3(0.575,0)
  silkscreen extent -0.03,-0.6 0.5,0.6, body extent -0.5,-0.5 0.5,0.5, height 0.5
DRV0006A [mm] "SON, 6-Leads, Body 2x2mm, Pitch 0.65mm, Thermal Pad 1.6x1mm, TI Recommended"
  rrect33% 0.45x0.3 smd: 1(-0.975,0.65) 2(-0.975,0) 3(-0.975,-0.65) 4(0.975,-0.65) 5(0.975,0) 6(0.975,0.65)
  rrect14% 1x0.7 on Bottom Paste: 7(0,-0.45) 7(0,0.45)
  rrect10% 1x1.6 smd paste-0.5: 7(0,0)
  silkscreen extent -1.05,-1.2 1.05,1.2, body extent -1.05,-1.05 1.05,1.05, height 0.81
DSN2_0603 [mm] "SMD, 2-Leads, Body 1.6x0.8mm"
  rect 0.52x0.7 smd: 1(-0.64,0)
  rect 1.05x0.7 smd: 2(0.275,0)
  silkscreen extent -1.4,-0.75 0.8,0.75, body extent -0.8,-0.4 0.8,0.4, height 0.31
ECS_CSM-3X [mm] "ECS"
  rect 3.5x1.2 smd: 1(-2.75,0) 2(2.75,0)
  silkscreen extent -3.6,-2.05 3.6,2.05, body extent -3.65,-2.1 3.65,2.1, height 2.3
FCC_disclaimer [mil]
Fiducial10-20#1 [mm]
  round 1 smd mask+0.5: 1(0,0.051)
  SSTXRX1 keep-out circle w1.178: c0,0 r0.5
Fiducial10-20#2 [mm]
  round 1 smd mask+0.5: 1(0,0)
  SSTXRX1 keep-out circle w1.178: c0,0 r0.5
Foxconn_JPD113D-LBA21 [mm] "Connector, DC Power Jack, R/A, 3 Pos, TH"
  rrect8% 1.2x2.7 hole 0.8 slot 1.8 at 90 deg: 1(-2.08,14.35)
  rrect100% 1.2x2.7 hole 0.8 slot 1.8 at 90 deg: 2(2.08,14.35)
  rrect100% 0.9x2.1 hole 0.6 slot 1.4 at 90 deg: 3(0,14.35)
  rrect100% 0.9x2.6 hole 0.6 slot 2.1 at 90 deg: 4(-6.35,9.25) 5(6.35,9.25)
  rrect100% 1.05x3.1 hole 0.7 slot 2.6 at 90 deg: 6(-6.35,12.45) 7(6.35,12.45)
  rrect100% 1.05x3.45 hole 0.7 slot 2.3 at 90 deg: 8(-6.35,2.95) 9(6.35,2.95)
  rrect11% 0.92x2 smd: MP1(-3.518,13.438) MP2(3.518,13.438)
  rrect15% 0.65x1.2 smd: MP3(-5.677,6.098) MP4(5.677,6.098)
  Keep-Out Layer board cut-out: -5.2,0 -5.2,11.85 -5.146,12.05 -5,12.196 -4.8,12.25 -4.8,12.25 4.8,12.25 5,12.196 5.146,12.05 5.2,11.85 5.2,11.85 5.2,0
  body extent -6.75,0 6.75,16.15, height 8.05
FUSE_SSQ [mm] "Bel Fuse"
  rect 2x3.18 smd: 1(-2.5,0) 2(2.5,0)
  silkscreen extent -1.27,-1.32 1.27,1.32, body extent -3.17,-1.32 3.17,1.32, height 2.64
Hirose_ZX62RD-AB-5P8 [mm] "Connector, Receptacle, Micro-USB Type AB, R/A, Bottom Mount SMT"
  rect 0.4x1.35 smd: 1(1.3,2.8) 2(0.65,2.8) 3(0,2.8) 4(-0.65,2.8) 5(-1.3,2.8)
  oval 1.05x1.25 hole 0.65 slot 0.85 at 90 deg: 6(2.225,3.125) 7(-2.225,3.125)
  oval 1.225x1.9 hole 0.825 slot 1.5 at 90 deg: 8(4.088,0) 9(-4.088,0)
  rect 2.9x1.9 smd: 10(0,0)
  SSTXRX1 region: -4.088,0.95 -3.3,0.95 -3.3,-0.95 -4.088,-0.95
  SSTXRX1 region: 4.088,-0.95 3.3,-0.95 3.3,0.95 4.088,0.95
  silkscreen extent -3.75,1.27 3.75,3.27, body extent -4.17,-2.62 4.18,3.27, height 2.74
Keystone_5019 [mm] "Test Point, Miniature, SMT"
  rect 3.8x2.03 smd: 1(0,0)
  silkscreen extent -2.31,-1.42 2.31,1.42, body extent -1.91,-1.02 1.9,1.02, height 2.29
LQFP64_N [mm] "Thin QFP, 64-Leads, Body 10x10mm, Pitch 0.5mm, IPC Medium Density"
  oval 1.8x0.3 smd: 1(-5.55,3.75) 2(-5.55,3.25) 3(-5.55,2.75) 4(-5.55,2.25) 5(-5.55,1.75) 6(-5.55,1.25) 7(-5.55,0.75) 8(-5.55,0.25) 9(-5.55,-0.25) 10(-5.55,-0.75) 11(-5.55,-1.25) 12(-5.55,-1.75) 13(-5.55,-2.25) 14(-5.55,-2.75) 15(-5.55,-3.25) 16(-5.55,-3.75) 33(5.55,-3.75) 34(5.55,-3.25) 35(5.55,-2.75) 36(5.55,-2.25) 37(5.55,-1.75) 38(5.55,-1.25) 39(5.55,-0.75) 40(5.55,-0.25) 41(5.55,0.25) 42(5.55,0.75) 43(5.55,1.25) 44(5.55,1.75) 45(5.55,2.25) 46(5.55,2.75) 47(5.55,3.25) 48(5.55,3.75)
  oval 0.3x1.8 smd: 17(-3.75,-5.55) 18(-3.25,-5.55) 19(-2.75,-5.55) 20(-2.25,-5.55) 21(-1.75,-5.55) 22(-1.25,-5.55) 23(-0.75,-5.55) 24(-0.25,-5.55) 25(0.25,-5.55) 26(0.75,-5.55) 27(1.25,-5.55) 28(1.75,-5.55) 29(2.25,-5.55) 30(2.75,-5.55) 31(3.25,-5.55) 32(3.75,-5.55) 49(3.75,5.55) 50(3.25,5.55) 51(2.75,5.55) 52(2.25,5.55) 53(1.75,5.55) 54(1.25,5.55) 55(0.75,5.55) 56(0.25,5.55) 57(-0.25,5.55) 58(-0.75,5.55) 59(-1.25,5.55) 60(-1.75,5.55) 61(-2.25,5.55) 62(-2.75,5.55) 63(-3.25,5.55) 64(-3.75,5.55)
  silkscreen extent -5.67,-4.25 4.25,4.58, body extent -5,-5 5,5, height 1.6
LTST-C193_Blue [mm] "SMD, 2-Leads, Body1.6x0.8mm"
  rect 0.8x0.8 smd: 1(-0.75,0) 2(0.75,0)
  silkscreen extent -1.2,-0.9 1.85,0.9, body extent -0.85,-0.45 0.85,0.45, height 0.45
"LW QH8G_White" [mm] "SMD, 2-Leads, Body 1x0.5mm"
  rect 0.6x0.6 smd paste-0.3: 1(-0.55,0) 2(0.55,0)
  silkscreen extent 1.1,-0.4 1.3,0.4, body extent -0.55,-0.3 0.55,0.3, height 0.4
MUA08A_N [mm] "TSOP, 8-Leads, Body 3x3mm, Pitch 0.65mm, IPC Medium Density"
  oval 1.7x0.45 smd: 1(-2.1,0.975) 2(-2.1,0.325) 3(-2.1,-0.325) 4(-2.1,-0.975) 5(2.1,-0.975) 6(2.1,-0.325) 7(2.1,0.325) 8(2.1,0.975)
  silkscreen extent -2.22,-1.55 0.85,1.87, body extent -1.6,-1.6 1.6,1.6, height 1.09
"PowerPAK_SO-8 _Dual" [mil] "Vishay"
  rect 50x24 smd: 1(-105,75) 2(-105,25) 3(-105,-25) 4(-105,-75)
  rect 40x24 smd: 5(110,-75) 6(110,-25) 7(110,25) 8(110,75)
  SSTXRX1 region: -48,77 102,77 102,12 -48,12
  SSTXRX1 region: -48,-12 102,-12 102,-77 -48,-77
  silkscreen extent -115,-98 70,125, body extent -118,-99 118,99, height 44
RSH0056E [mm] "SMD, 56-Leads, Body 7x7mm, Pitch 0.4mm"
  rrect67% 0.8x0.3 smd paste-0.05 mask-0.05: 1(-3.35,2.6) 2(-3.35,2.2) 3(-3.35,1.8) 4(-3.35,1.4) 5(-3.35,1) 6(-3.35,0.6) 7(-3.35,0.2) 8(-3.35,-0.2) 9(-3.35,-0.6) 10(-3.35,-1) 11(-3.35,-1.4) 12(-3.35,-1.8) 13(-3.35,-2.2) 14(-3.35,-2.6) 29(3.35,-2.6) 30(3.35,-2.2) 31(3.35,-1.8) 32(3.35,-1.4) 33(3.35,-1) 34(3.35,-0.6) 35(3.35,-0.2) 36(3.35,0.2) 37(3.35,0.6) 38(3.35,1) 39(3.35,1.4) 40(3.35,1.8) 41(3.35,2.2) 42(3.35,2.6)
  rrect67% 0.3x0.8 smd paste-0.05 mask-0.05: 15(-2.6,-3.35) 16(-2.2,-3.35) 17(-1.8,-3.35) 18(-1.4,-3.35) 19(-1,-3.35) 20(-0.6,-3.35) 21(-0.2,-3.35) 22(0.2,-3.35) 23(0.6,-3.35) 24(1,-3.35) 25(1.4,-3.35) 26(1.8,-3.35) 27(2.2,-3.35) 28(2.6,-3.35) 43(2.6,3.35) 44(2.2,3.35) 45(1.8,3.35) 46(1.4,3.35) 47(1,3.35) 48(0.6,3.35) 49(0.2,3.35) 50(-0.2,3.35) 51(-0.6,3.35) 52(-1,3.35) 53(-1.4,3.35) 54(-1.8,3.35) 55(-2.2,3.35) 56(-2.6,3.35)
  rrect6% 1.75x2.6 smd paste-2.2: 57(-1.875,1.45)
  rrect16% 1.47x1.15 on Top Paste: 57(-1.875,2.125) 57(-1.875,0.775) 58(-1.875,-0.8) 58(-1.875,-2.15)
  rrect6% 1.75x2.55 smd paste-2.2: 58(-1.875,-1.475)
  rrect12% 1.47x1.12 on Top Paste: 59(0.215,1.98) 59(0.215,0.66) 59(0.215,-0.66) 59(0.215,-1.98) 59(1.885,1.98) 59(1.885,-0.66) 59(1.885,0.66) 59(1.885,-1.98)
  rrect3% 3.4x5.5 smd paste-2.2: 59(1.05,0)
  SSTXRX1 region: -3.75,-2.6 -2.95,-2.6 -2.95,-2.2 -3.75,-2.2
  SSTXRX1 region: -3.75,-1.8 -2.95,-1.8 -2.95,-1.4 -3.75,-1.4
  SSTXRX1 region: -3.75,1.4 -2.95,1.4 -2.95,1.8 -3.75,1.8
  SSTXRX1 region: -3.75,2.2 -2.95,2.2 -2.95,2.6 -3.75,2.6
  silkscreen extent -3.7,-3.7 3.7,3.7, body extent -3.57,-3.57 3.57,3.57, height 1.01
RSH0056E_NSMD [mm] "SMD, 56-Leads, Body 7x7mm, Pitch 0.4mm"
  rrect67% 0.8x0.3 smd paste-0.05 mask-0.05: 1(-3.35,2.6) 2(-3.35,2.2) 3(-3.35,1.8) 4(-3.35,1.4) 11(-3.35,-1.4) 12(-3.35,-1.8) 13(-3.35,-2.2) 14(-3.35,-2.6)
  rrect50% 0.7x0.2 smd: 5(-3.35,1) 6(-3.35,0.6) 7(-3.35,0.2) 8(-3.35,-0.2) 9(-3.35,-0.6) 10(-3.35,-1) 29(3.35,-2.6) 30(3.35,-2.2) 31(3.35,-1.8) 32(3.35,-1.4) 33(3.35,-1) 34(3.35,-0.6) 35(3.35,-0.2) 36(3.35,0.2) 37(3.35,0.6) 38(3.35,1) 39(3.35,1.4) 40(3.35,1.8) 41(3.35,2.2) 42(3.35,2.6)
  rrect50% 0.2x0.7 smd: 15(-2.6,-3.35) 16(-2.2,-3.35) 17(-1.8,-3.35) 18(-1.4,-3.35) 19(-1,-3.35) 20(-0.6,-3.35) 21(-0.2,-3.35) 22(0.2,-3.35) 23(0.6,-3.35) 24(1,-3.35) 25(1.4,-3.35) 26(1.8,-3.35) 27(2.2,-3.35) 28(2.6,-3.35) 43(2.6,3.35) 44(2.2,3.35) 45(1.8,3.35) 46(1.4,3.35) 47(1,3.35) 48(0.6,3.35) 49(0.2,3.35) 50(-0.2,3.35) 51(-0.6,3.35) 52(-1,3.35) 53(-1.4,3.35) 54(-1.8,3.35) 55(-2.2,3.35) 56(-2.6,3.35)
  rrect6% 1.75x2.6 smd paste-2.2: 57(-1.875,1.45)
  rrect16% 1.47x1.15 on Top Paste: 57(-1.875,2.125) 57(-1.875,0.775) 58(-1.875,-0.8) 58(-1.875,-2.15)
  rrect6% 1.75x2.55 smd paste-2.2: 58(-1.875,-1.475)
  rrect12% 1.47x1.12 on Top Paste: 59(0.215,1.98) 59(0.215,0.66) 59(0.215,-0.66) 59(0.215,-1.98) 59(1.885,1.98) 59(1.885,-0.66) 59(1.885,0.66) 59(1.885,-1.98)
  rrect3% 3.4x5.5 smd paste-2.2: 59(1.05,0)
  SSTXRX1 region: -3.75,-2.6 -2.95,-2.6 -2.95,-2.2 -3.75,-2.2
  SSTXRX1 region: -3.75,-1.8 -2.95,-1.8 -2.95,-1.4 -3.75,-1.4
  SSTXRX1 region: -3.75,1.4 -2.95,1.4 -2.95,1.8 -3.75,1.8
  SSTXRX1 region: -3.75,2.2 -2.95,2.2 -2.95,2.6 -3.75,2.6
  silkscreen extent -3.7,-3.7 3.7,3.7, body extent -3.57,-3.57 3.57,3.57, height 1.01
Samtec_SSQ-104-03-x-D [mm] "Receptacle, 2.54mm, 4x2, TH"
  rect 1.55x1.55 hole 1.02: 1(-3.81,1.27)
  round 1.55 hole 1.02: 2(-3.81,-1.27) 3(-1.27,1.27) 4(-1.27,-1.27) 5(1.27,1.27) 6(1.27,-1.27) 7(3.81,1.27) 8(3.81,-1.27)
  silkscreen extent -5.44,-2.57 5.44,2.57, body extent -5.33,-2.48 5.33,2.48, height 8.51
SOD-128 [mm] "SMD, 2-Leads, Body 4x2.7mm, Height 1.1mm"
  rect 1.4x2.1 smd paste-0.1: 1(-2.2,0) 2(2.2,0)
  silkscreen extent -3.45,-1.45 2.95,1.45, body extent -2.5,-1.35 2.5,1.35, height 1.11
SOP-8_150MIL [mm] "SOP, 8-Leads, Body 5.03x4mm, Pitch 1.27mm"
  rrect18% 1.4x0.57 smd: 1(-2.75,1.905) 2(-2.75,0.635) 3(-2.75,-0.635) 4(-2.75,-1.905) 5(2.75,-1.905) 6(2.75,-0.635) 7(2.75,0.635) 8(2.75,1.905)
  silkscreen extent -2,-2.5 2,2.79, body extent -2,-2.5 2,2.5, height 1.76
SOT-23 [mm] "SOT23, 3-Leads, Body 2.9x1.3mm, Pitch 0.95mm, Lead Span 2.5mm, IPC Medium Density"
  rrect50% 1x0.6 smd: 1(-1.2,0.95) 2(-1.2,-0.95) 3(1.2,0)
  silkscreen extent -1.63,-1.5 0.7,1.5, body extent -1.16,-1.45 1.21,1.45, height 1
SOT-23-6 [mm] "SOT23, 6-Leads, Body 3.0x1.7mm, Pitch 0.95mm, Lead Span 2.9mm, IPC Medium Density"
  rect 1.1x0.65 smd: 1(-1.2,0.95) 2(-1.2,0) 3(-1.2,-0.95) 4(1.2,-0.95) 5(1.2,0) 6(1.2,0.95)
  silkscreen extent -0.25,-1.55 0.25,1.55, body extent -1.5,-1.5 1.5,1.5, height 1.3
SOT-323 [mm] "Diodes Inc recommended land pattern.  2016-02-24"
  rrect21% 0.6x0.47 smd: 1(-0.95,0.65) 2(-0.95,-0.65) 3(0.95,0)
  silkscreen extent -1.14,-1.22 0.77,1.22, body extent -1.13,-1.13 1.12,1.12, height 1.13
SW_434121025816 [mm] "SMD, 2-Leads, Body 6x3.9mm, Pitch 6.5mm"
  rect 1.5x1.4 smd: 1(-3.25,0) 2(3.25,0)
  silkscreen extent -3,-1.95 3,1.95, body extent -3.65,-1.95 3.65,1.95, height 2.5
TNPW0603 [mm] "Vishay"
  rect 0.5x0.9 smd: 1(-0.75,0) 2(0.75,0)
  silkscreen extent -0.2,-0.6 0.2,0.6, body extent -0.85,-0.47 0.85,0.47, height 0.55
TRANS_AOS_DFN3X3 [mm] "Alpha & Omega Semi."
  rect 0.5x0.35 smd mask+0.07: 1(-1.4,0.975) 2(-1.4,0.325) 3(-1.4,-0.325) 4(-1.4,-0.975)
  rect 0.5x0.4 smd mask+0.07: 5(1.4,-0.975) 6(1.4,-0.325) 7(1.4,0.325) 8(1.4,0.975)
  SSTXRX1 region: -0.63,1.225 1.35,1.225 1.35,-1.225 -0.63,-1.225
  SSTXRX1 region: -0.215,-1.13 0.215,-1.13 0.215,-1.605 -0.215,-1.605
  SSTXRX1 region: -0.215,1.605 0.215,1.605 0.215,1.13 -0.215,1.13
  silkscreen extent -2.27,-1.7 1.7,1.7, body extent -1.55,-1.55 1.55,1.55, height 0.9
TSW-103-07-G-S [mm] "Samtec 100mil, 1x3, 230 mil above insulator"
  rrect50% 1.65x1.65 hole 1.016: 1(-2.54,0)
  round 1.65 hole 1.016: 2(0,0) 3(2.54,0)
  body extent -3.81,-1.27 3.81,1.27, height 8.38
WE-LHMI_4020 [mm] "WERTH"
  rrect7% 1.5x2.4 smd: 1(-1.85,0) 2(1.85,0)
  silkscreen extent -2.2,-2.2 2.2,2.2, body extent -2.15,-2.15 2.15,2.15, height 2
WEEE_Minimum [mil] "WEEElie bin"
  silkscreen extent -95,-172 99,104
WL-SMCW_GREEN [mm] "WURTH"
  rect 0.8x0.8 smd: 1(-0.8,0) 2(0.8,0)
  silkscreen extent -1.9,-0.8 1.2,0.8, body extent -0.85,-0.45 0.85,0.45, height 0.8
Wurth_632_723_300_011 [mm] "Connector, Receptacle, USB Type C, R/A"
  rect 0.3x1.2 smd: A1(-2.75,10.58) A2(-2.25,10.58) A3(-1.75,10.58) A4(-1.25,10.58) A5(-0.75,10.58) A6(-0.25,10.58) A7(0.25,10.58) A8(0.75,10.58) A9(1.25,10.58) A10(1.75,10.58) A11(2.25,10.58) A12(2.75,10.58)
  round 0.55 hole 0.4: B1(2.8,9.32) B2(2.4,8.62) B3(1.6,8.62) B4(1.2,9.32) B5(0.8,8.62) B6(0.4,9.32) B7(-0.4,9.32) B8(-0.8,8.62) B9(-1.2,9.32) B10(-1.6,8.62) B11(-2.4,8.62) B12(-2.8,9.32) M1(2,9.32) M2(-2,9.32)
  rrect100% 1x1.6 hole 0.6 slot 1.2 at 90 deg: S1(-4.27,8.18) S2(-4.27,3.45) S3(4.27,3.45) S4(4.27,8.18)
  silkscreen extent -4.37,0.15 4.37,10.36, body extent -4.37,-0.96 4.37,10.83, height 3.07
Wurth_60900213421 [mil] "Shunt, 2.54mm, Black"
  round 1 on Mech3: 0(0,0)
  body extent -98,-48 98,48, height 338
